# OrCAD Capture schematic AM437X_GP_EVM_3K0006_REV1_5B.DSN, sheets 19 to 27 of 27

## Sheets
19 Pg24: Keypad/LED's: size C
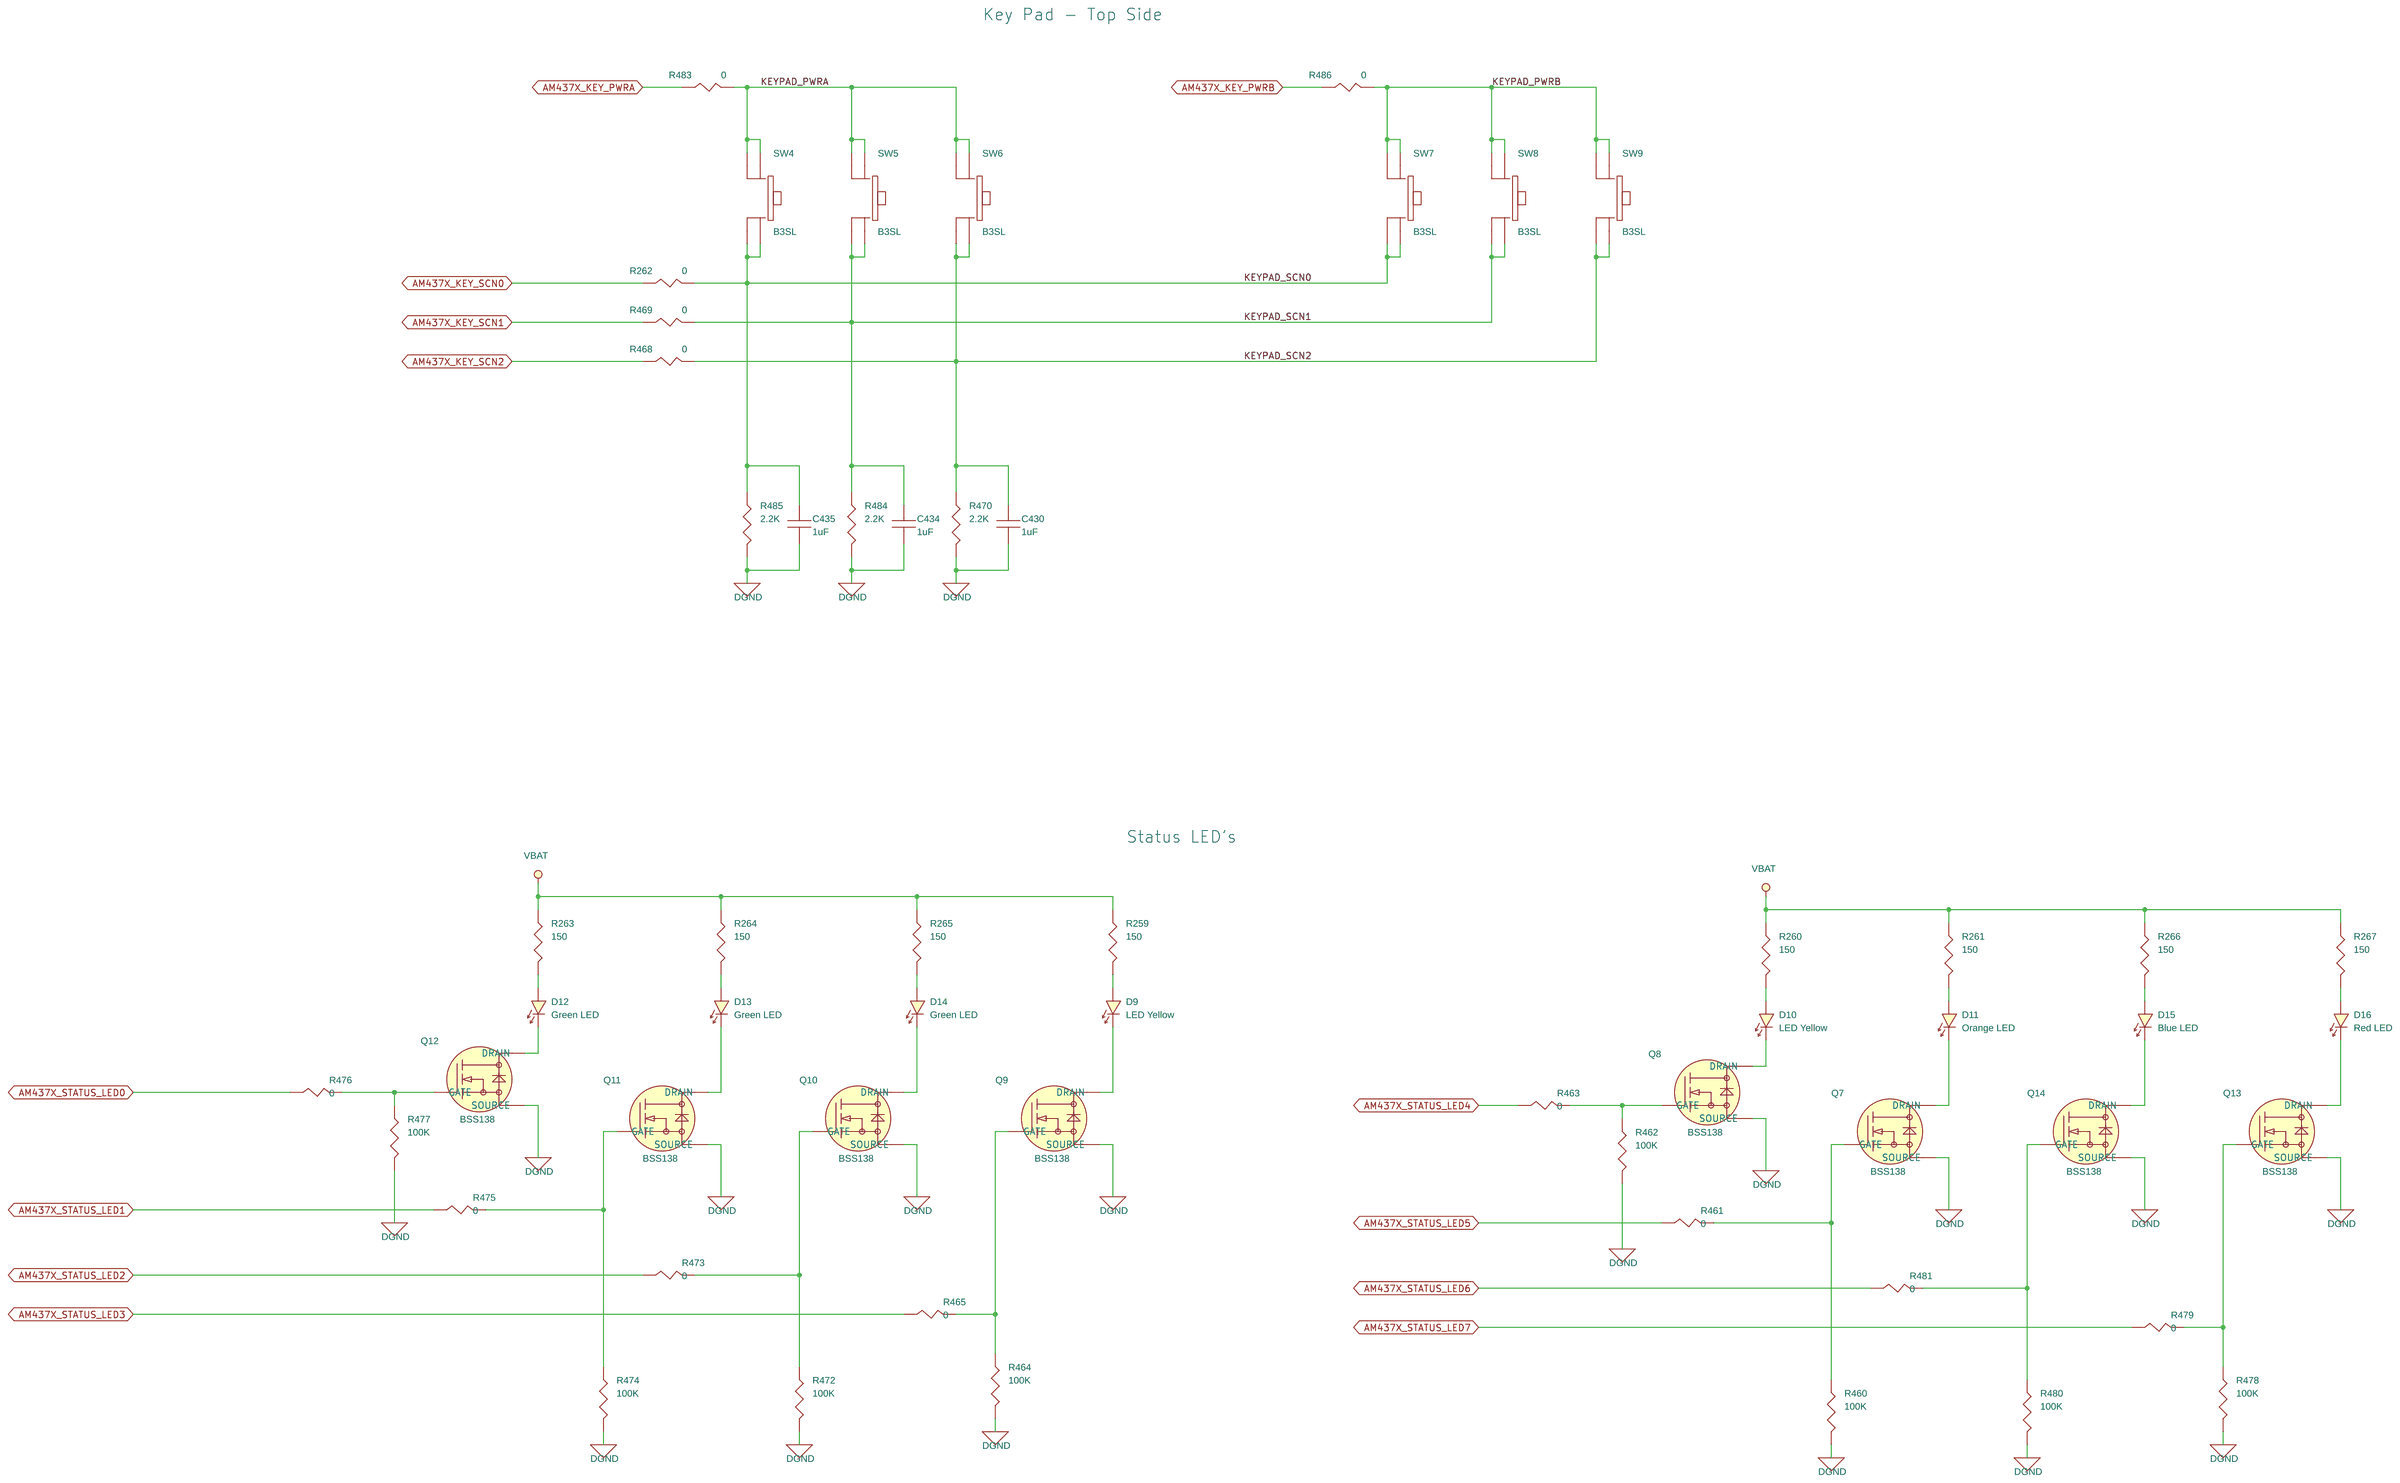
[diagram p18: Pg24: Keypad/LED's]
20 Pg27: Power Monitor: size C
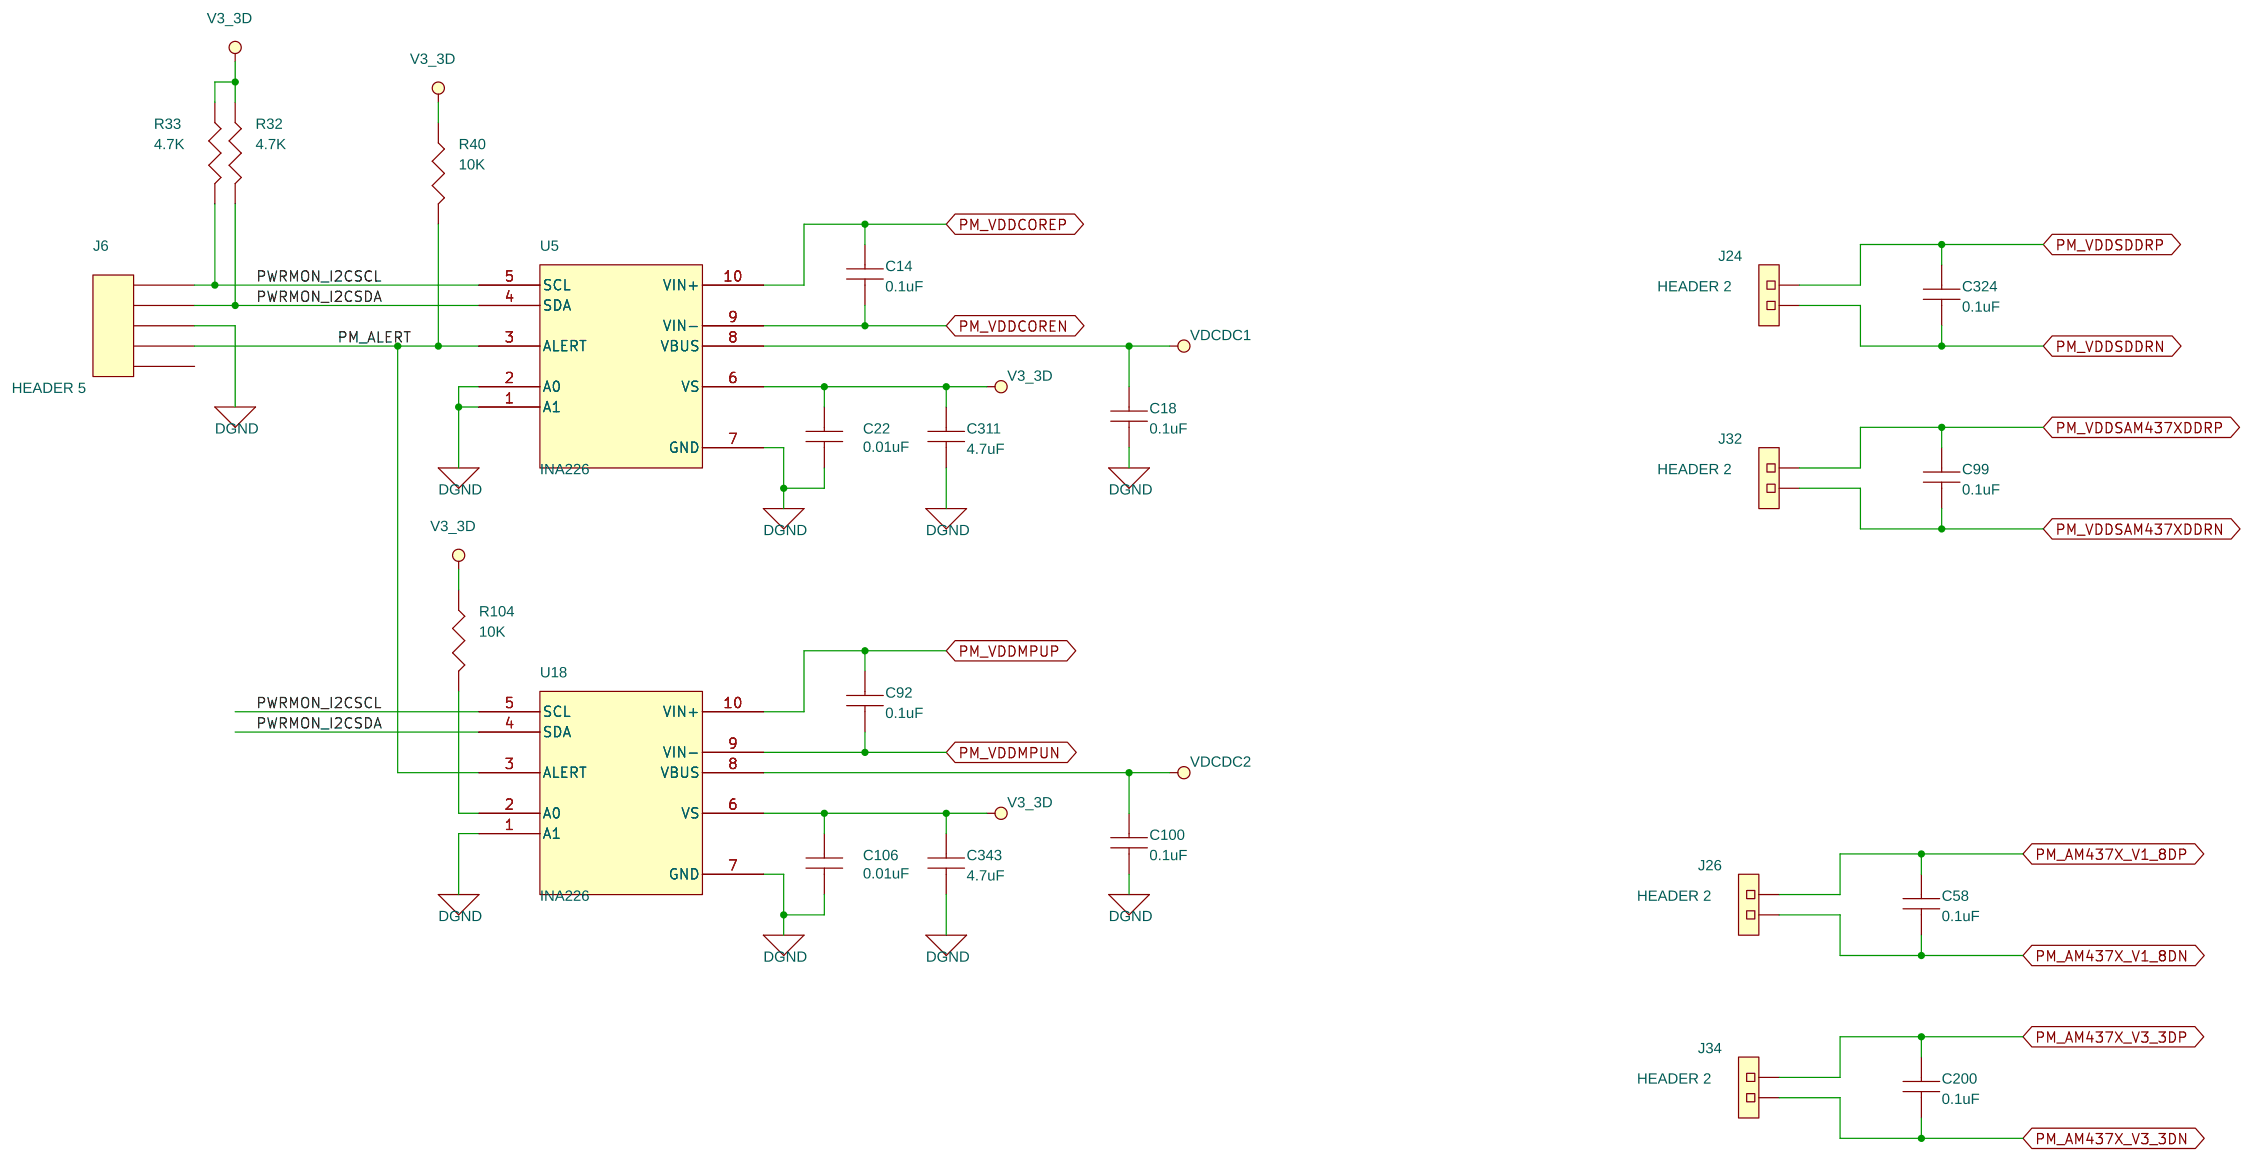
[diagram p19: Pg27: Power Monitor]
21 Pg23: Unused pins/GPIO: size C
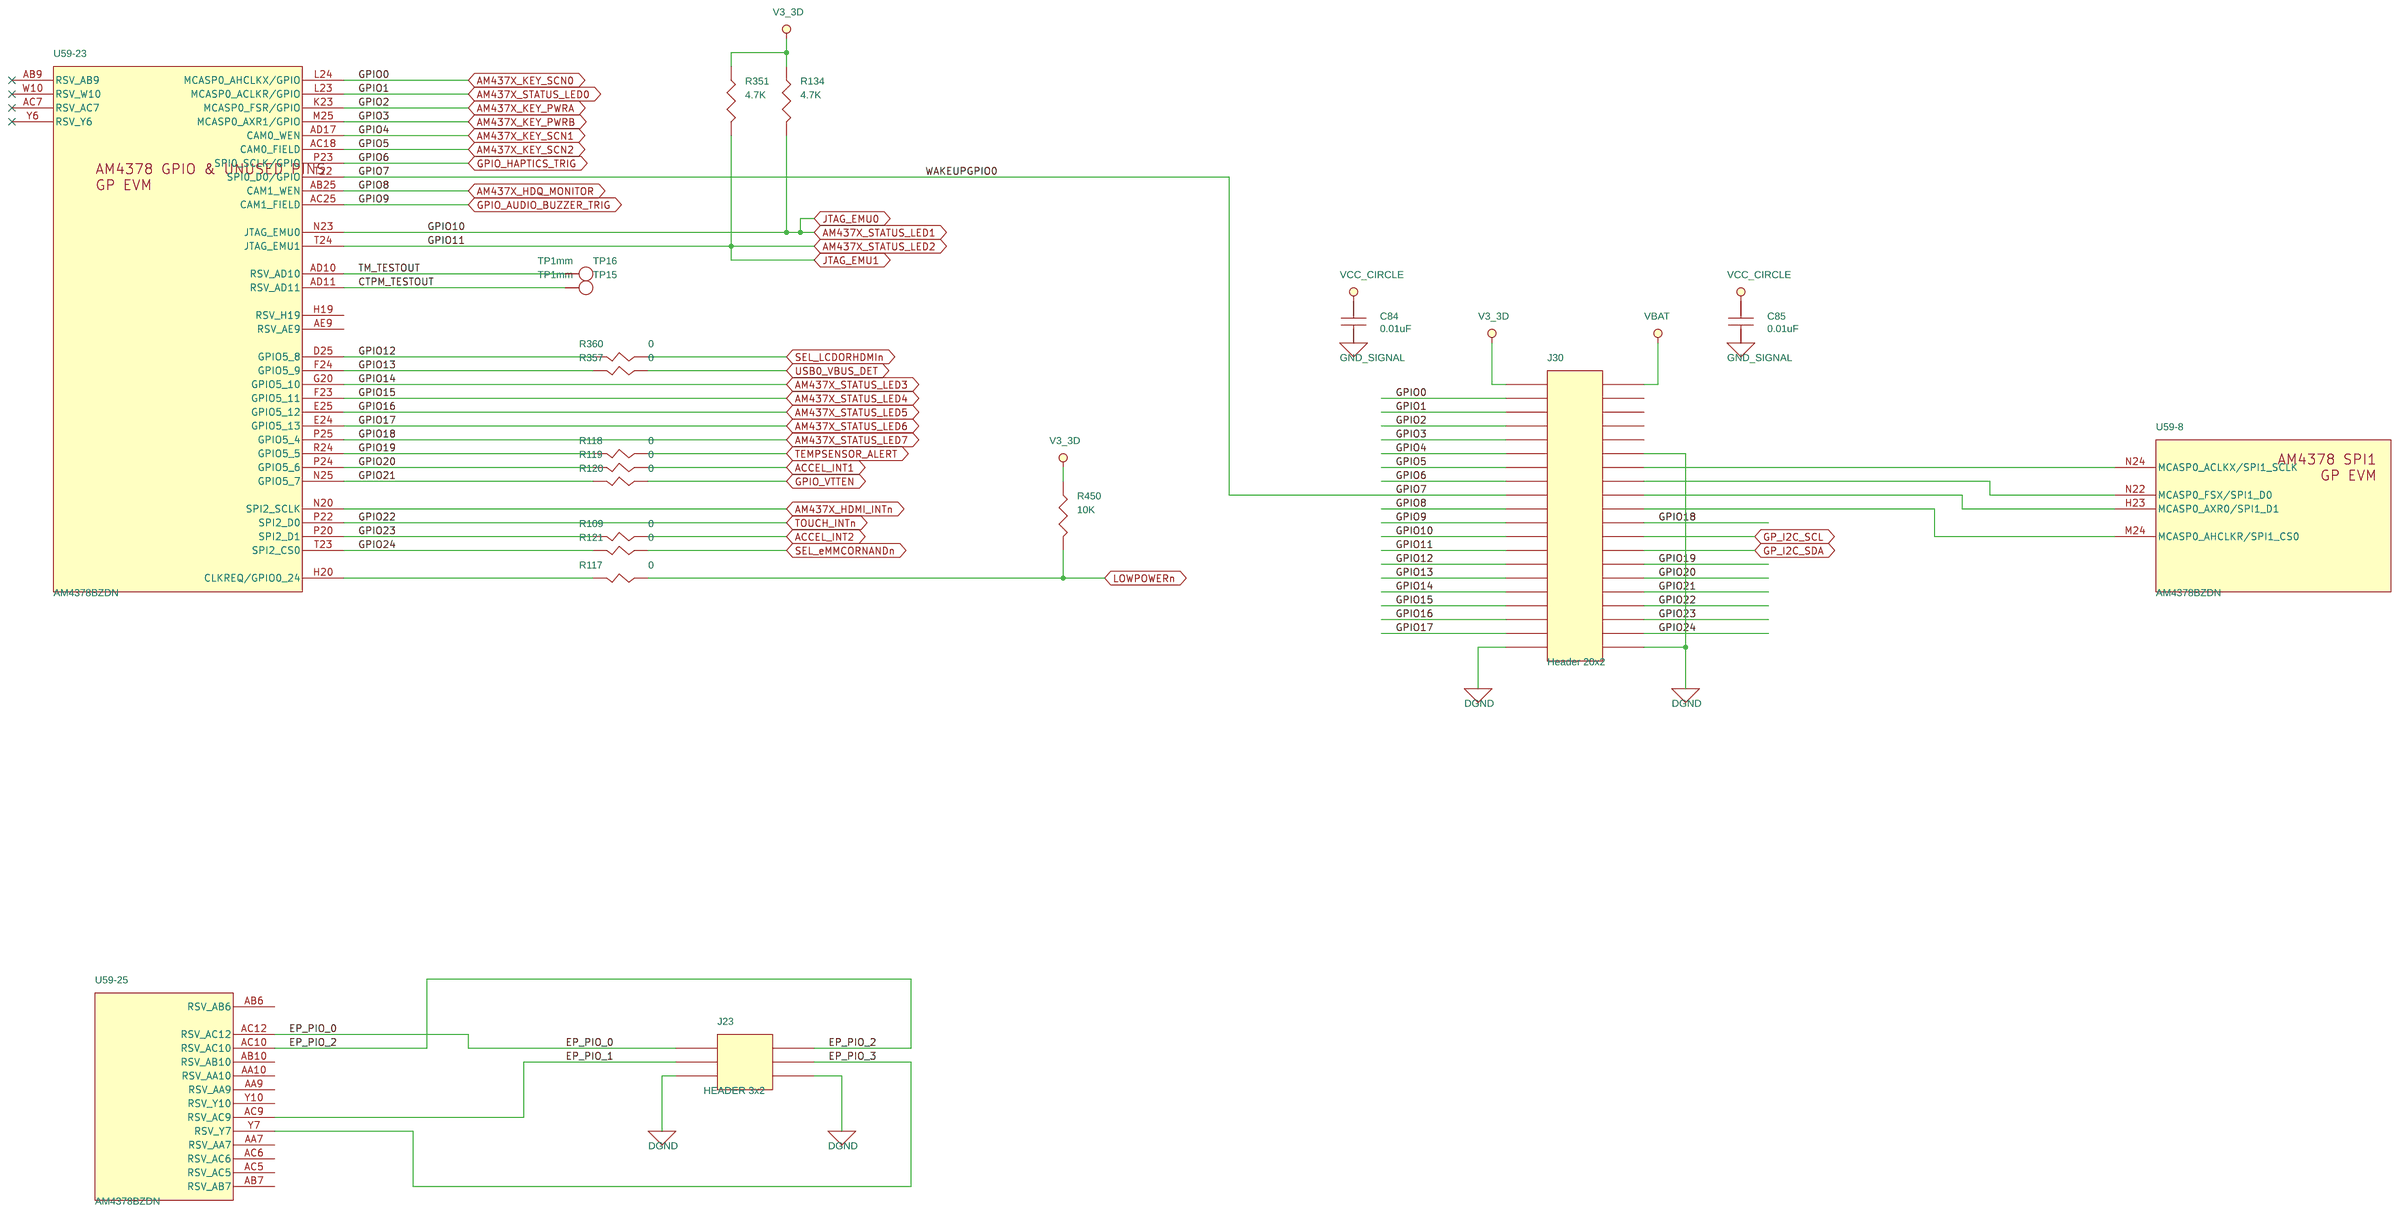
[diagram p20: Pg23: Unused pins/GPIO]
22 Pg08: SDMMC0 Interface: size C
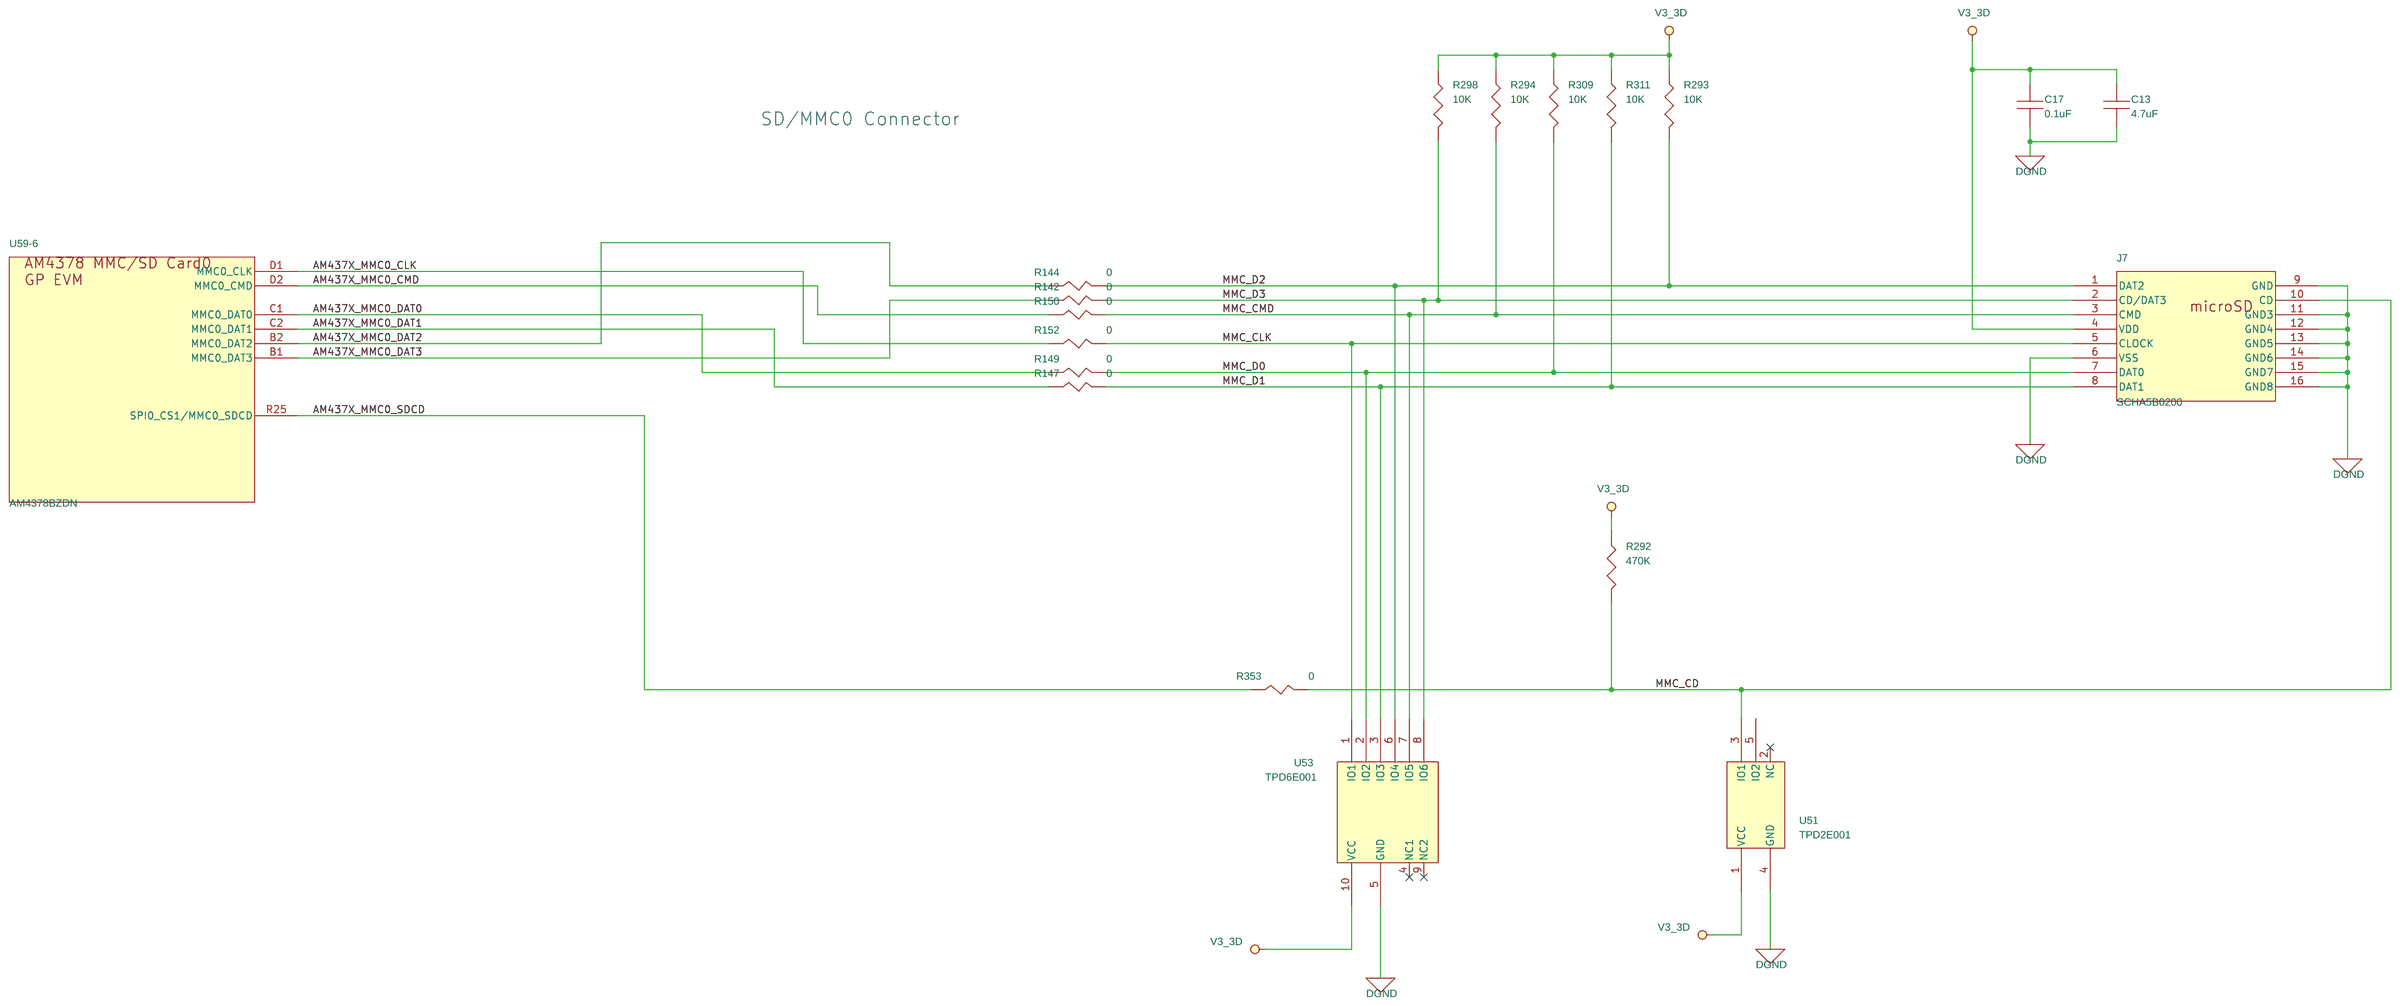
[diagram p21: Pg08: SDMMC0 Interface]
23 Pg04: Power Supply - PMIC: size C
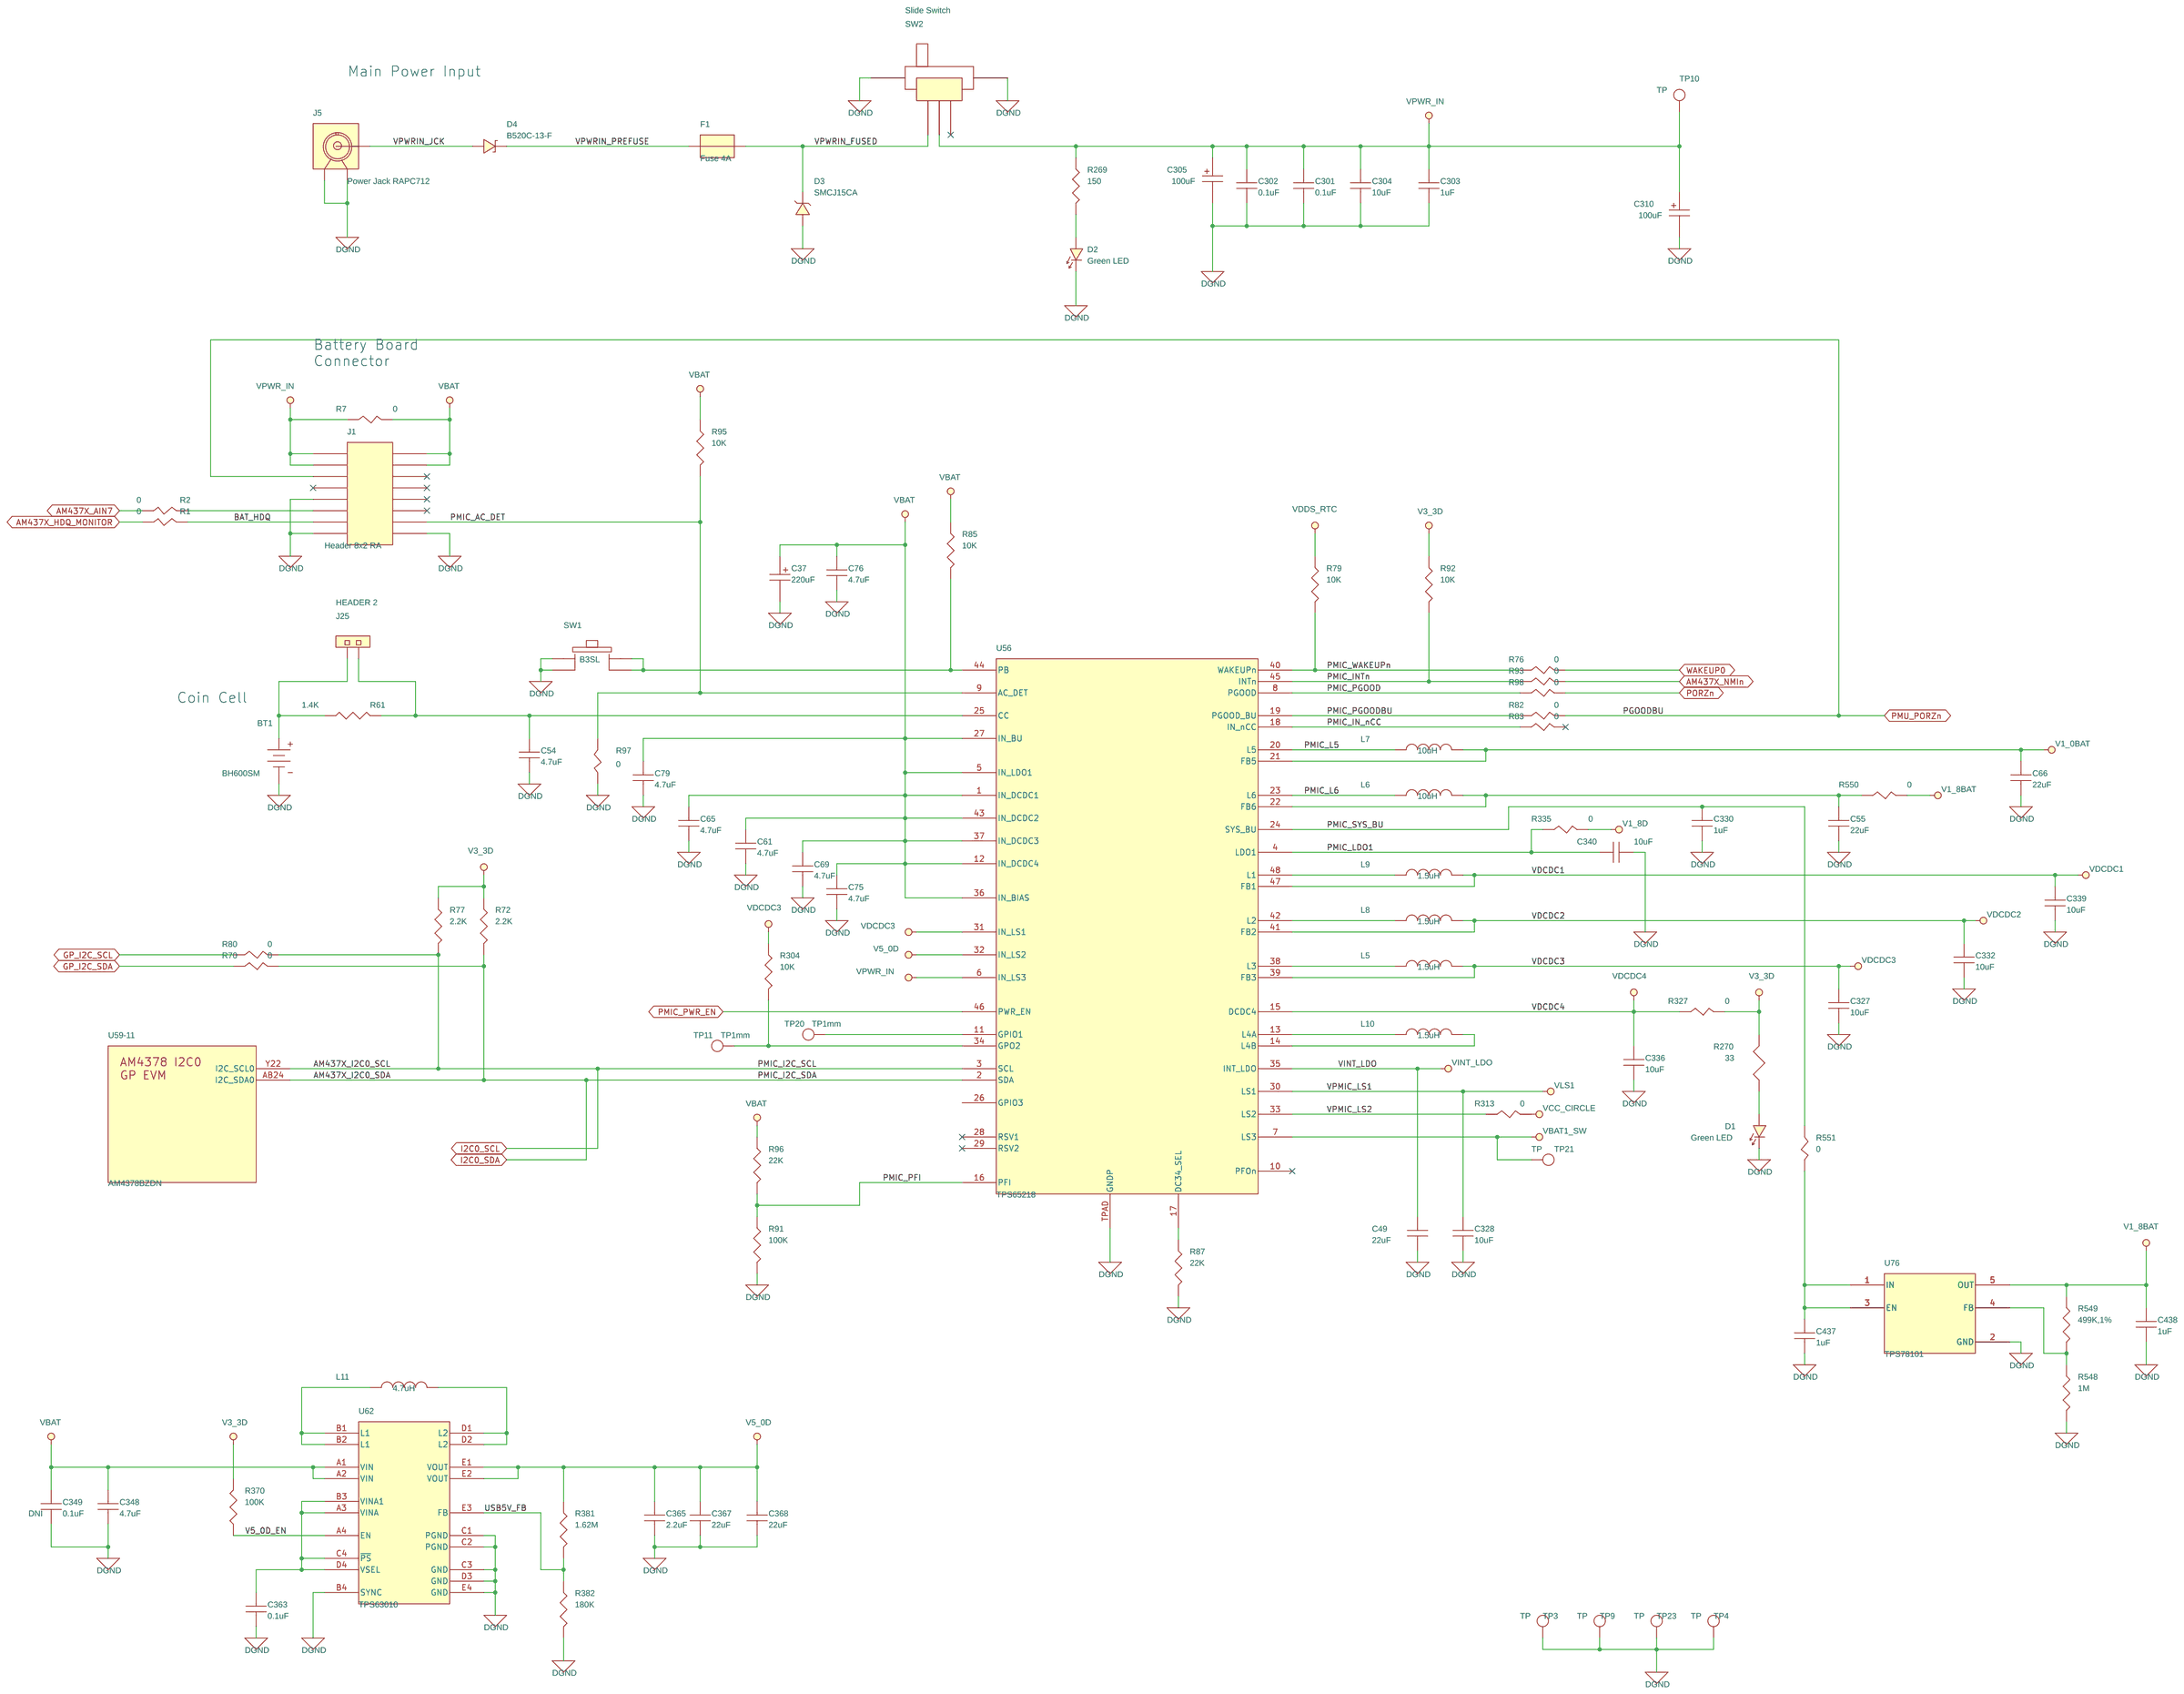
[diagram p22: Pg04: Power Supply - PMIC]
24 Pg02: Processor subsystem: size C
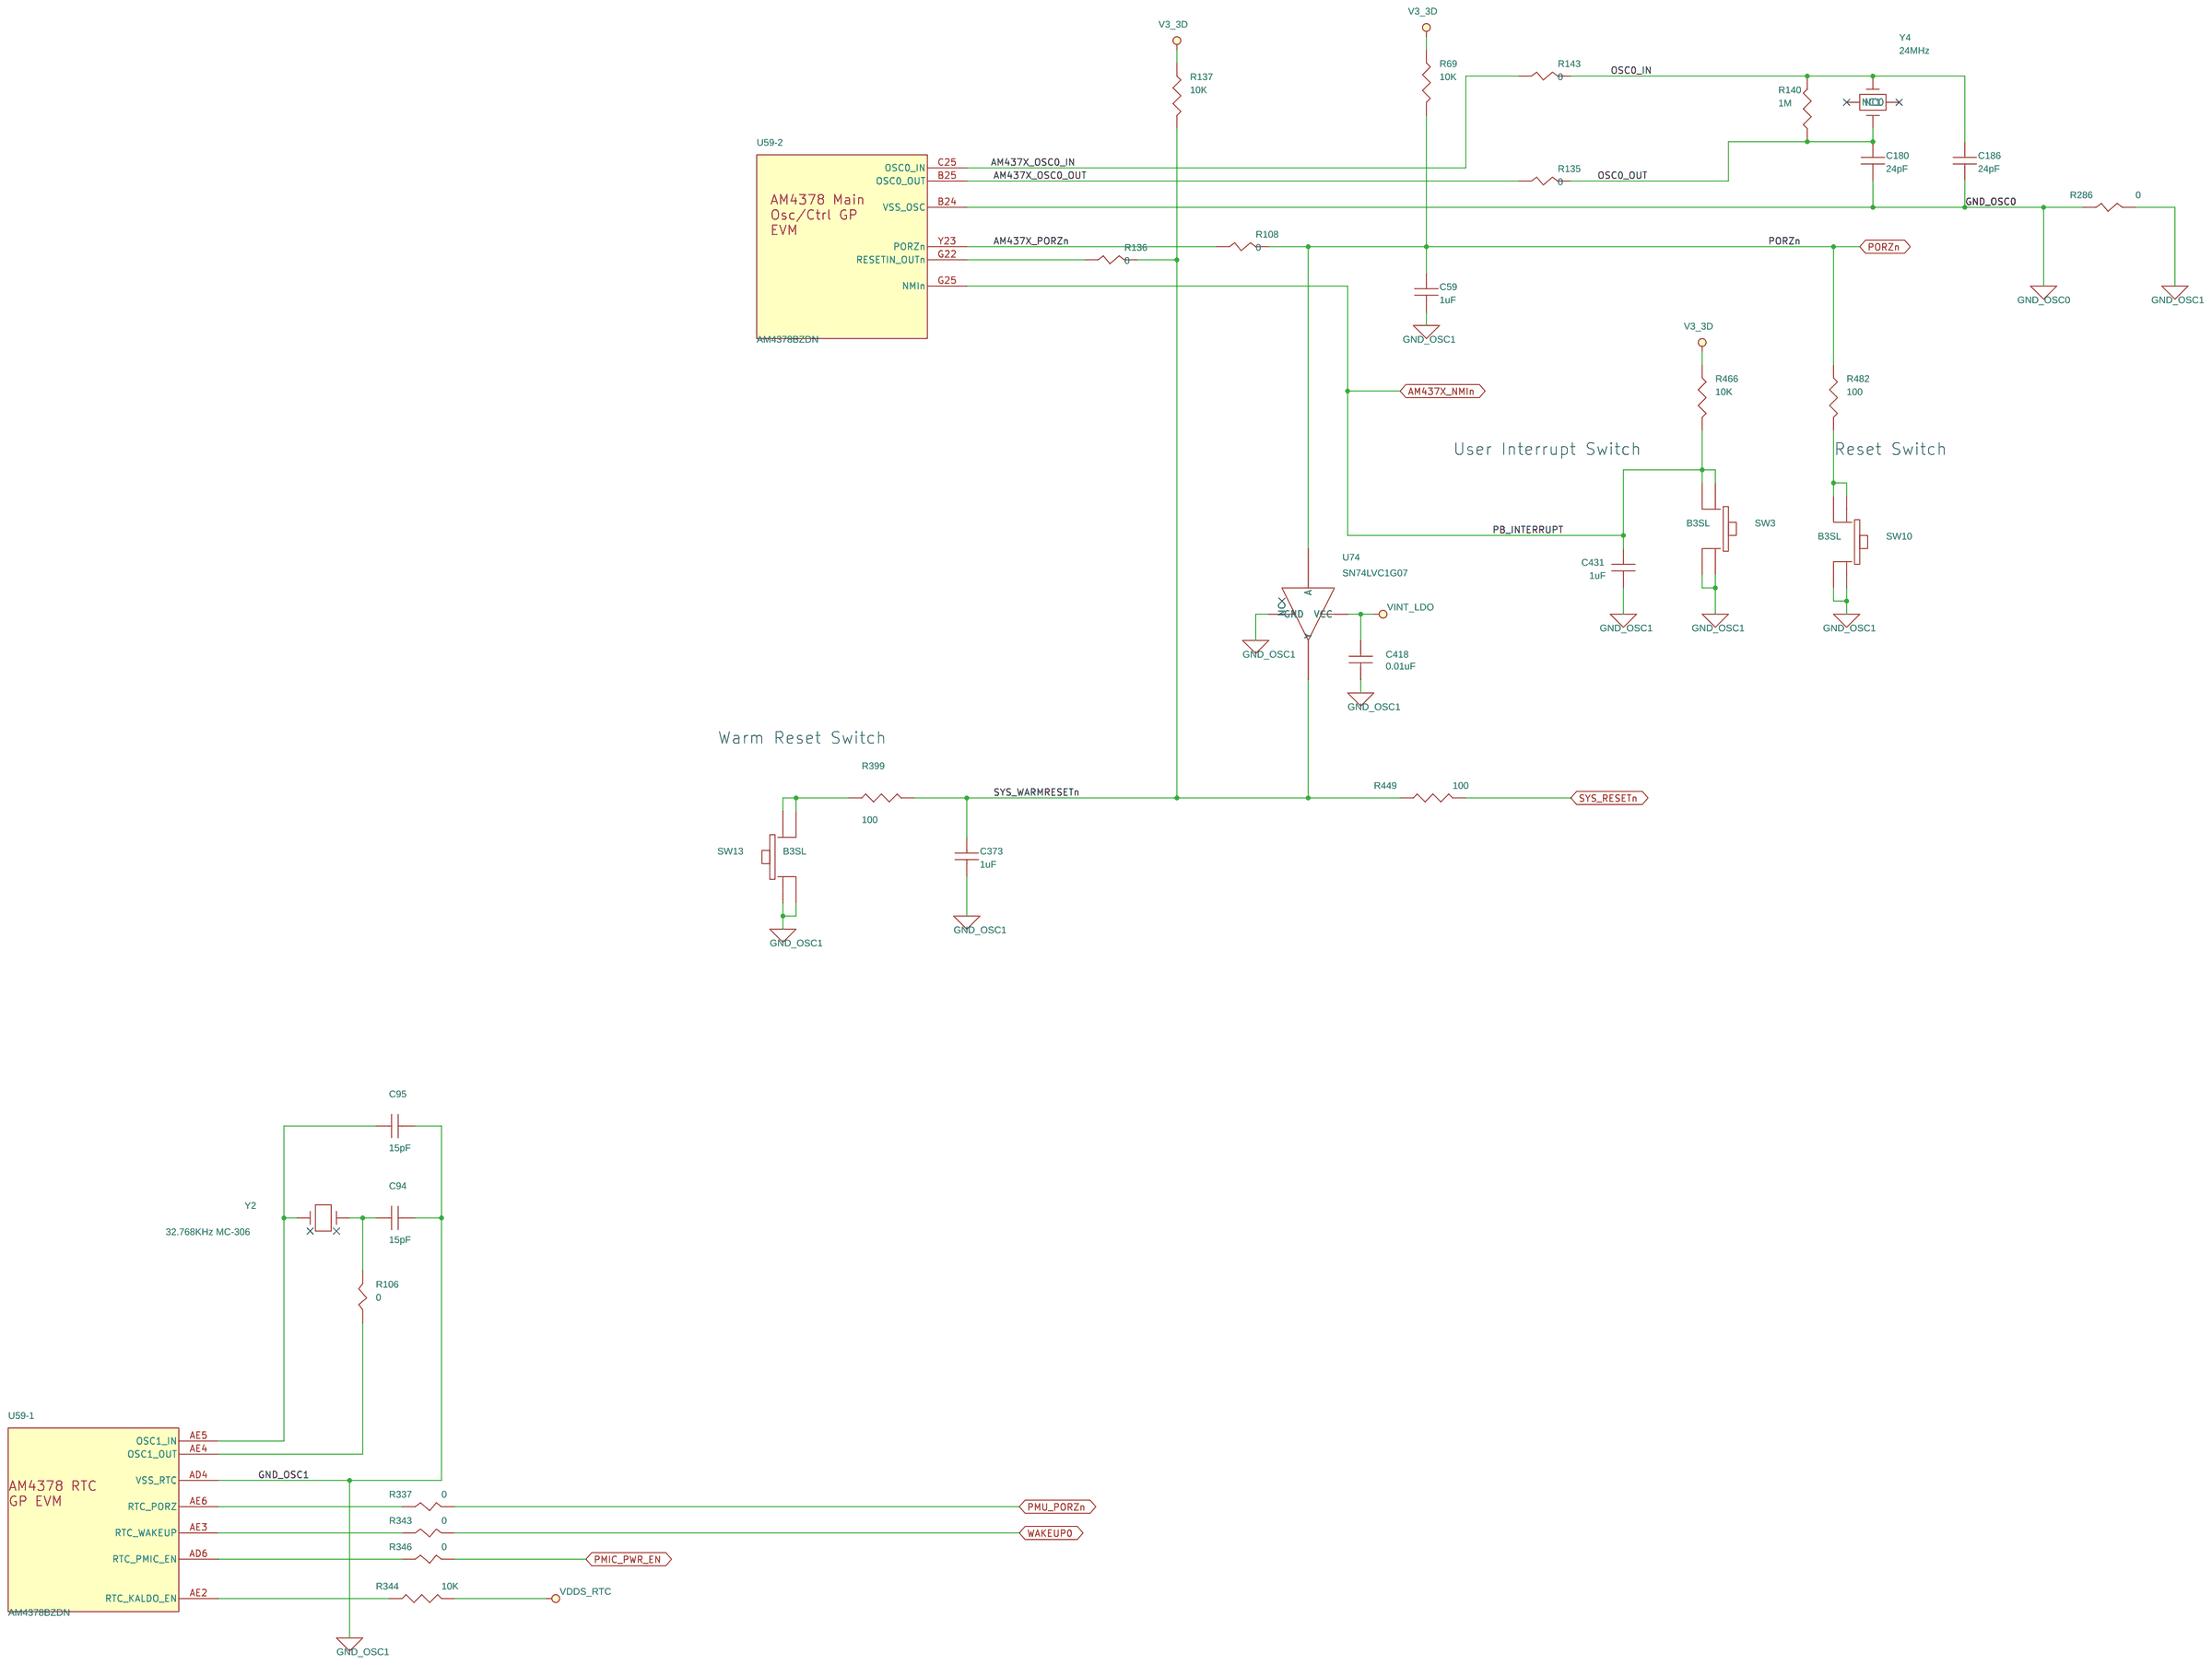
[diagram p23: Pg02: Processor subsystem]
25 Pg05: NAND Flash Memory & eMMC: size C
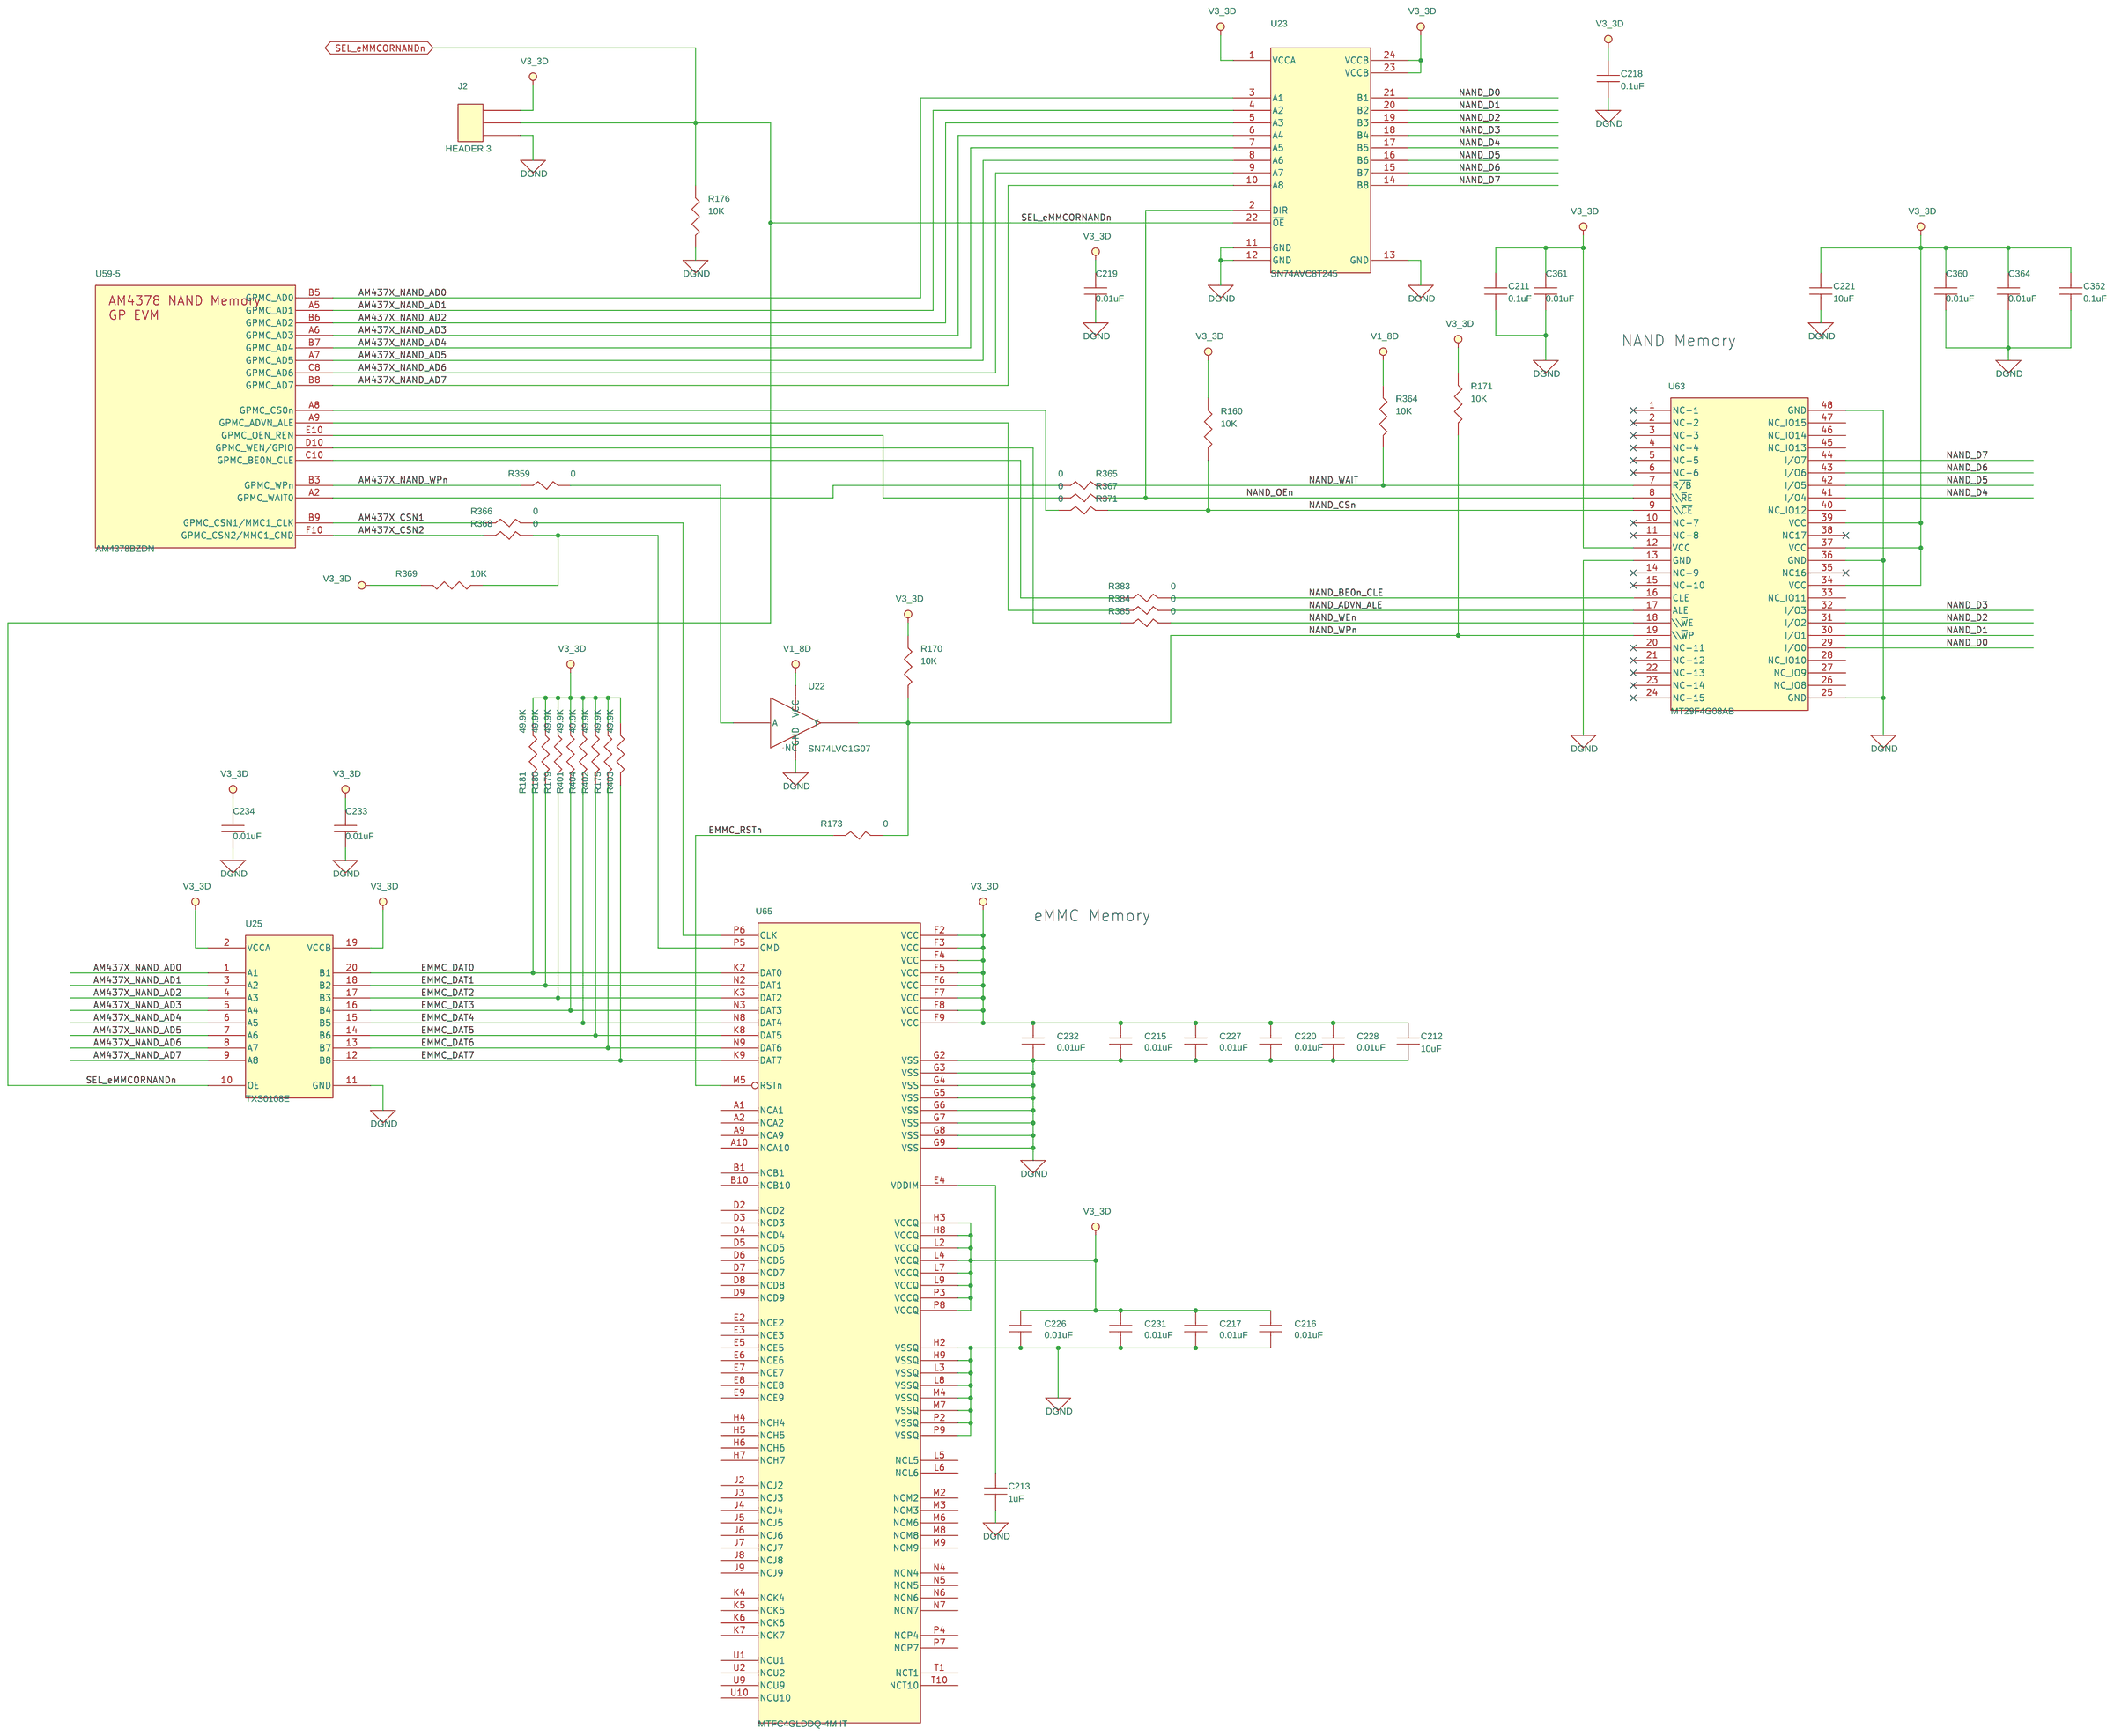
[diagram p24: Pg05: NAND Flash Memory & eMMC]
26 Pg20: Secondary RTC Osc/Ctrl: size C
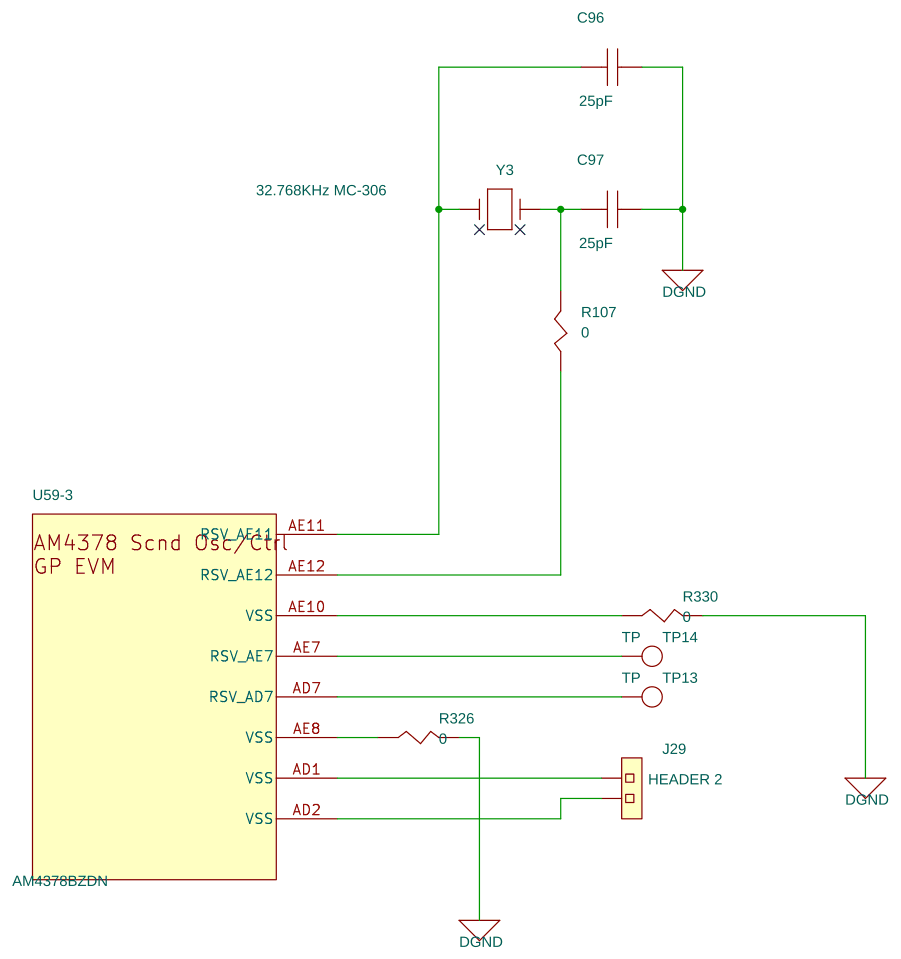
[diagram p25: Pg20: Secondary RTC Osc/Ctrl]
27 Pg10: Sensors, Buzzer, Haptics: size C
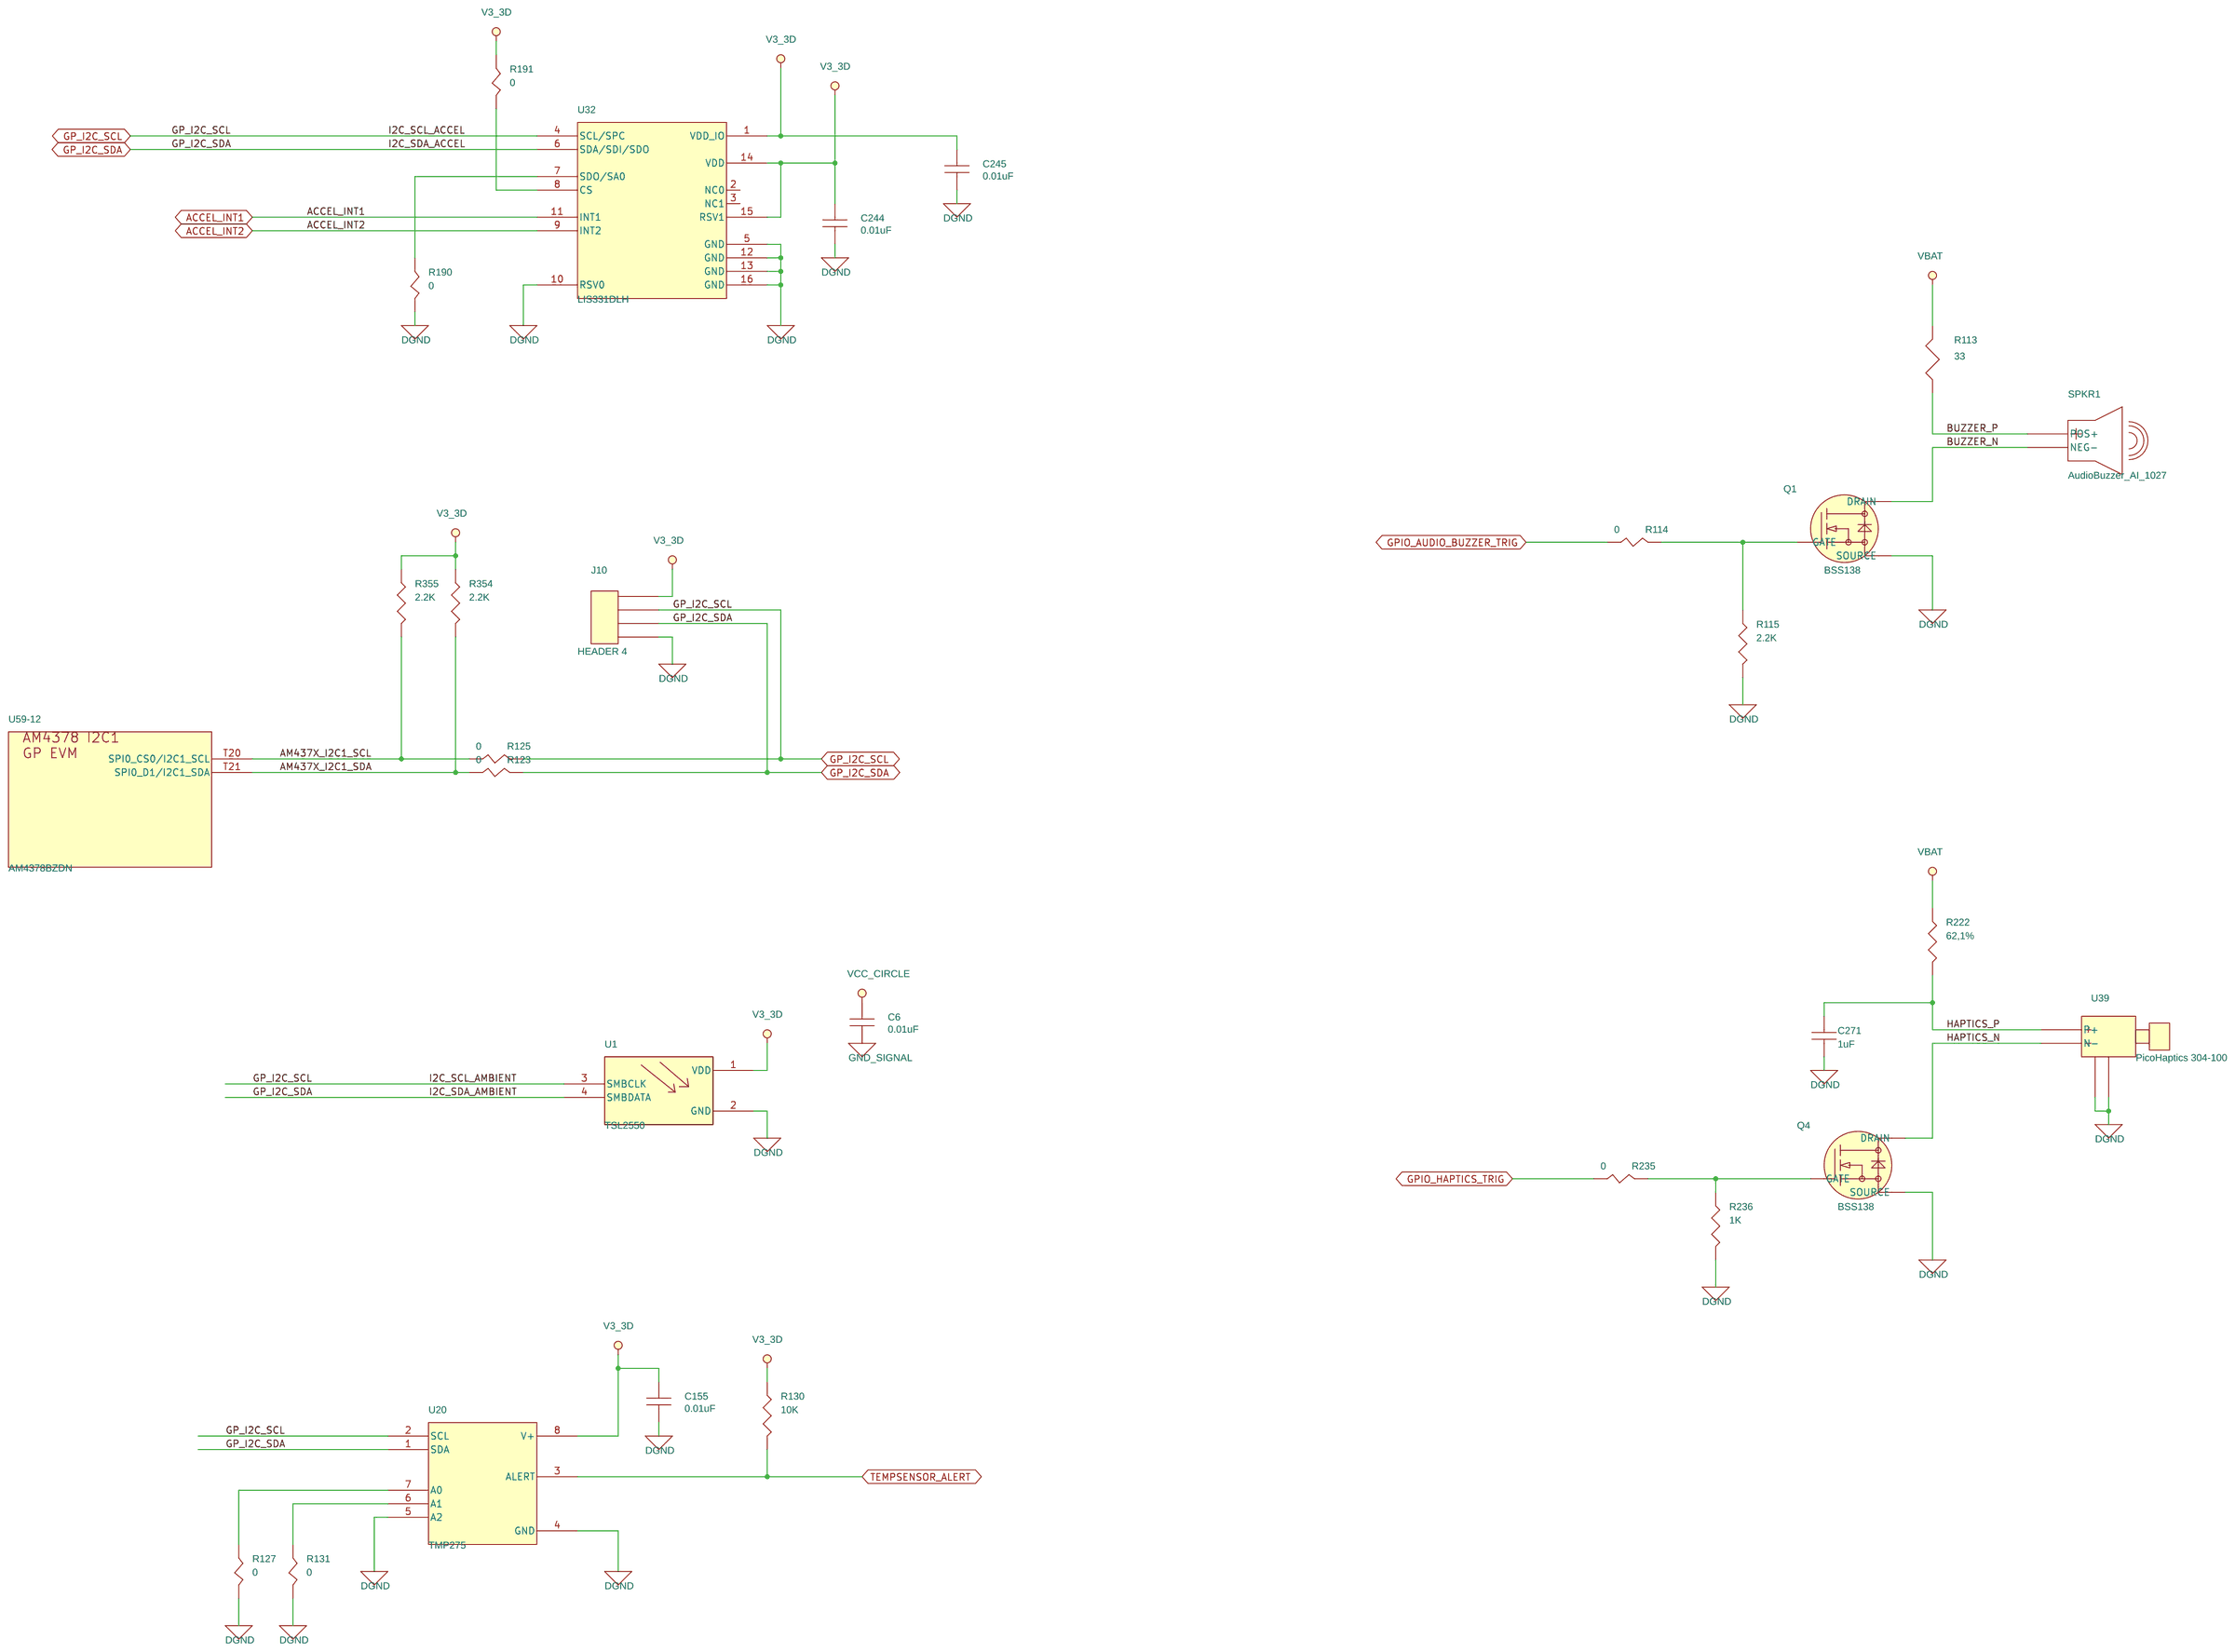
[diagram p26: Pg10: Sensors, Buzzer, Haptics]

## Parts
sheet Pg02: Processor subsystem
C59  1uF  [SM-7351-CAP-0402]
C94  15pF  [SM-7351-CAP-0402]
C95  15pF  [SM-7351-CAP-0402]
C180  24pF  [SM-7351-CAP-0402]
C186  24pF  [SM-7351-CAP-0402]
C373  1uF  [SM-7351-CAP-0402]
C418  0.01uF  [SM-7351-CAP-0402]
C431  1uF  [SM-7351-CAP-0402]
R69  10K  [SM-7351-RES-0402]
R106  0  [SM-7351-RES-0402]
R108  0  [SM-7351-RES-0402]
R135  0  [SM-7351-RES-0402]
R136  0  [SM-7351-RES-0402]
R137  10K  [SM-7351-RES-0402]
R140  1M  [SM-7351-RES-0402]
R143  0  [SM-7351-RES-0402]
R286  0  [SM-7351-RES-0402]
R337  0  [SM-7351-RES-0402]
R343  0  [SM-7351-RES-0402]
R344  10K  [SM-7351-RES-0402]
R346  0  [SM-7351-RES-0402]
R399  100  [SM-7351-RES-0402]
R449  100  [SM-7351-RES-0402]
R466  10K  [SM-7351-RES-0402]
R482  100  [SM-7351-RES-0402]
SW3  B3SL  [SW_B3SL-1022P]
SW10  B3SL  [SW_B3SL-1022P]
SW13  B3SL  [SW_B3SL-1022P]
U74  SN74LVC1G07  [SC70-5-43M]
Y2  32.768KHz MC-306  [MC-306]
Y4  24MHz  [XTAL2X3-30M]
sheet Pg04: Power Supply - PMIC
BT1  BH600SM  [bh600sm]
C37  220uF  [smd7343-122m]
C49  22uF  [SM-7351-CAP-0805]
C54  4.7uF  [SM-7351-CAP-0603]
C55  22uF  [SM-7351-CAP-0603]
C61  4.7uF  [SM-7351-CAP-0603]
C65  4.7uF  [SM-7351-CAP-0603]
C66  22uF  [SM-7351-CAP-0603]
C69  4.7uF  [SM-7351-CAP-0603]
C75  4.7uF  [SM-7351-CAP-0603]
C76  4.7uF  [SM-7351-CAP-0603]
C79  4.7uF  [SM-7351-CAP-0603]
C301  0.1uF  [SM-7351-CAP-0402]
C302  0.1uF  [SM-7351-CAP-0402]
C303  1uF  [SM-7351-CAP-0603]
C304  10uF  [SM-7351-CAP-0805]
C305  100uF  [SM-7351-CAP-smdcan]
C310  100uF  [SM-7351-CAP-smdcan]
C327  10uF  [SM-7351-CAP-0805]
C328  10uF  [SM-7351-CAP-0805]
C330  1uF  [SM-7351-CAP-0402]
C332  10uF  [SM-7351-CAP-0805]
C336  10uF  [SM-7351-CAP-0805]
C339  10uF  [SM-7351-CAP-0805]
C340  10uF  [SM-7351-CAP-0805]
C348  4.7uF  [SM-7351-CAP-0603]
C349  0.1uF  [SM-7351-CAP-0402]
C363  0.1uF  [SM-7351-CAP-0402]
C365  2.2uF  [SM-7351-CAP-0402]
C367  22uF  [SM-7351-CAP-0805]
C368  22uF  [SM-7351-CAP-0805]
C437  1uF  [SM-7351-CAP-0603]
C438  1uF  [SM-7351-CAP-0603]
D1  Green LED  [sm_led_0805]
D2  Green LED  [sm_led_0805]
D3  SMCJ15CA  [SMCJ15CA]
D4  B520C-13-F  [B520C-13-F]
F1  Fuse 4A  [smdfuseblk]
J1  Header 8x2 RA  [HDR2X8RA-201M]
J5  Power Jack RAPC712  [RAPC712]
J25  HEADER 2  [header_2x1]
L5  1.5uH  [IND_SPM3012T]
L6  10uH  [ind-mlz2012-57m]
L7  10uH  [ind-mlz2012-57m]
L8  1.5uH  [IND_SPM3012T]
L9  1.5uH  [IND_SPM3012T]
L10  1.5uH  [IND_SPM3012T]
L11  4.7uH  [smd_slf7055t]
R1  0  [SM-7351-RES-0402]
R2  0  [SM-7351-RES-0402]
R7  0  [SM-7351-RES-1210]
R61  1.4K  [SM-7351-RES-0402]
R70  0  [SM-7351-RES-0402]
R72  2.2K  [sm-7351-res-0402]
R76  0  [SM-7351-RES-0402]
R77  2.2K  [sm-7351-res-0402]
R79  10K  [SM-7351-RES-0402]
R80  0  [SM-7351-RES-0402]
R82  0  [SM-7351-RES-0402]
R83  0  [SM-7351-RES-0402]
R85  10K  [SM-7351-RES-0402]
R87  22K  [SM-7351-RES-0402]
R91  100K  [SM-7351-RES-0402]
R92  10K  [SM-7351-RES-0402]
R93  0  [SM-7351-RES-0402]
R95  10K  [SM-7351-RES-0402]
R96  22K  [SM-7351-RES-0402]
R97  0  [SM-7351-RES-0402]
R98  0  [SM-7351-RES-0402]
R269  150  [SM-7351-RES-0402]
R270  33  [SM-7351-RES-0402]
R304  10K  [SM-7351-RES-0402]
R313  0  [SM-7351-RES-0402]
R327  0  [SM-7351-RES-0603]
R335  0  [SM-7351-RES-0603]
R370  100K  [SM-7351-RES-0402]
R381  1.62M  [SM-7351-RES-0402]
R382  180K  [SM-7351-RES-0402]
R548  1M  [SM-7351-RES-0402]
R549  499K,1%  [SM-7351-RES-0402]
R550  0  [SM-7351-RES-0402]
R551  0  [SM-7351-RES-0402]
SW1  B3SL  [SW_B3SL-1022P]
SW2  Slide Switch  [TH_SW_T551101]
TP3  TP  [TH_TP_5002]
TP4  TP  [TH_TP_5002]
TP9  TP  [TH_TP_5002]
TP10  TP  [TH_TP_5002]
TP11  TP1mm  [tp_smd1mmcircle]
TP20  TP1mm  [tp_smd1mmcircle]
TP21  TP  [TH_TP_5002]
TP23  TP  [TH_TP_5002]
U56  TPS65218  [qfn6x6-48-39m]
U62  TPS63010  [u_20_dsbga]
U76  TPS78101  [sot23-5-43m]
sheet Pg05: NAND Flash Memory & eMMC
C211  0.1uF  [SM-7351-CAP-0402]
C212  10uF  [SM-7351-CAP-0805]
C213  1uF  [SM-7351-CAP-0402]
C215  0.01uF  [SM-7351-CAP-0402]
C216  0.01uF  [SM-7351-CAP-0402]
C217  0.01uF  [SM-7351-CAP-0402]
C218  0.1uF  [SM-7351-CAP-0402]
C219  0.01uF  [SM-7351-CAP-0402]
C220  0.01uF  [SM-7351-CAP-0402]
C221  10uF  [SM-7351-CAP-0805]
C226  0.01uF  [SM-7351-CAP-0402]
C227  0.01uF  [SM-7351-CAP-0402]
C228  0.01uF  [SM-7351-CAP-0402]
C231  0.01uF  [SM-7351-CAP-0402]
C232  0.01uF  [SM-7351-CAP-0402]
C233  0.01uF  [SM-7351-CAP-0402]
C234  0.01uF  [SM-7351-CAP-0402]
C360  0.01uF  [SM-7351-CAP-0402]
C361  0.01uF  [SM-7351-CAP-0402]
C362  0.1uF  [SM-7351-CAP-0402]
C364  0.01uF  [SM-7351-CAP-0402]
J2  HEADER 3  [header_3x1]
R160  10K  [SM-7351-RES-0402]
R170  10K  [SM-7351-RES-0402]
R171  10K  [SM-7351-RES-0402]
R173  0  [SM-7351-RES-0402]
R175  49.9K  [SM-7351-RES-0402]
R176  10K  [SM-7351-RES-0402]
R179  49.9K  [SM-7351-RES-0402]
R180  49.9K  [SM-7351-RES-0402]
R181  49.9K  [SM-7351-RES-0402]
R359  0  [SM-7351-RES-0402]
R364  10K  [SM-7351-RES-0402]
R365  0  [SM-7351-RES-0402]
R366  0  [SM-7351-RES-0402]
R367  0  [SM-7351-RES-0402]
R368  0  [SM-7351-RES-0402]
R369  10K  [SM-7351-RES-0402]
R371  0  [SM-7351-RES-0402]
R383  0  [SM-7351-RES-0402]
R384  0  [SM-7351-RES-0402]
R385  0  [SM-7351-RES-0402]
R401  49.9K  [SM-7351-RES-0402]
R402  49.9K  [SM-7351-RES-0402]
R403  49.9K  [SM-7351-RES-0402]
R404  49.9K  [SM-7351-RES-0402]
U22  SN74LVC1G07  [SC70-5-43M]
U23  SN74AVC8T245  [TSSOP8x4-24-47m]
U25  TXS0108E  [u_20_pw]
U63  MT29F4G08AB  [skt-tsop48sm]
U65  MTFC4GLDDQ-4M IT  [bga18x14-100-55m]
sheet Pg08: SDMMC0 Interface
C13  4.7uF  [SM-7351-CAP-0603]
C17  0.1uF  [SM-7351-CAP-0402]
J7  SCHA5B0200  [SD-MICRO-SCHA5B0300]
R142  0  [SM-7351-RES-0402]
R144  0  [SM-7351-RES-0402]
R147  0  [SM-7351-RES-0402]
R149  0  [SM-7351-RES-0402]
R150  0  [SM-7351-RES-0402]
R152  0  [SM-7351-RES-0402]
R292  470K  [SM-7351-RES-0402]
R293  10K  [SM-7351-RES-0402]
R294  10K  [SM-7351-RES-0402]
R298  10K  [SM-7351-RES-0402]
R309  10K  [SM-7351-RES-0402]
R311  10K  [SM-7351-RES-0402]
R353  0  [SM-7351-RES-0402]
U51  TPD2E001  [U_5_DRL]
U53  TPD6E001  [U_10_RSE]
U59  AM4378BZDN  [AM437X_ZDN]  (sections -1,-10,-11,-12,-13,-14,-15,-16,-17,-18,-19,-2,-20,-21,-22,-23,-24,-25,-3,-4,-5,-6,-7,-8,-9)
sheet Pg10: Sensors, Buzzer, Haptics
C6  0.01uF  [SM-7351-CAP-0402]
C155  0.01uF  [SM-7351-CAP-0402]
C244  0.01uF  [SM-7351-CAP-0402]
C245  0.01uF  [SM-7351-CAP-0402]
C271  1uF  [SM-7351-CAP-0603]
J10  HEADER 4  [HDR1x4-330M]
Q1  BSS138  [SOT23-3]
Q4  BSS138  [SOT23-3]
R113  33  [SM-7351-RES-0402]
R114  0  [SM-7351-RES-0402]
R115  2.2K  [sm-7351-res-0402]
R123  0  [SM-7351-RES-0402]
R125  0  [SM-7351-RES-0402]
R127  0  [SM-7351-RES-0402]
R130  10K  [SM-7351-RES-0402]
R131  0  [SM-7351-RES-0402]
R190  0  [SM-7351-RES-0402]
R191  0  [SM-7351-RES-0402]
R222  62,1%  [sm-7351-res-0402]
R235  0  [SM-7351-RES-0402]
R236  1K  [SM-7351-RES-0402]
R354  2.2K  [sm-7351-res-0402]
R355  2.2K  [sm-7351-res-0402]
SPKR1  AudioBuzzer_AI_1027  [spkr_ai_1027]
U1  TSL2550  [smd4x3-4-59m]
U20  TMP275  [MSOP_dgk]
U32  LIS331DLH  [LGA16pin_3x3]
U39  PicoHaptics 304-100  [pico_304-100]
sheet Pg20: Secondary RTC Osc/Ctrl
C96  25pF  [SM-7351-CAP-0603]
C97  25pF  [SM-7351-CAP-0603]
J29  HEADER 2  [header_2x1]
R107  0  [SM-7351-RES-0402]
R326  0  [SM-7351-RES-0402]
R330  0  [SM-7351-RES-0402]
TP13  TP  [TH_TP_5002]
TP14  TP  [TH_TP_5002]
Y3  32.768KHz MC-306  [MC-306]
sheet Pg23: Unused pins/GPIO
C84  0.01uF  [SM-7351-CAP-0402]
C85  0.01uF  [SM-7351-CAP-0402]
J23  HEADER 3x2  [hdr2x3-330m]
J30  Header 20x2  [HDR2X20-330M]
R109  0  [SM-7351-RES-0402]
R117  0  [SM-7351-RES-0402]
R118  0  [SM-7351-RES-0402]
R119  0  [SM-7351-RES-0402]
R120  0  [SM-7351-RES-0402]
R121  0  [SM-7351-RES-0402]
R134  4.7K  [SM-7351-RES-0402]
R351  4.7K  [SM-7351-RES-0402]
R357  0  [SM-7351-RES-0402]
R360  0  [SM-7351-RES-0402]
R450  10K  [SM-7351-RES-0402]
TP15  TP1mm  [tp_smd1mmcircle]
TP16  TP1mm  [tp_smd1mmcircle]
sheet Pg24: Keypad/LED's
C430  1uF  [SM-7351-CAP-0402]
C434  1uF  [SM-7351-CAP-0402]
C435  1uF  [SM-7351-CAP-0402]
D9  LED Yellow  [sm_led_0805]
D10  LED Yellow  [sm_led_0805]
D11  Orange LED  [sm_led_0805]
D12  Green LED  [sm_led_0805]
D13  Green LED  [sm_led_0805]
D14  Green LED  [sm_led_0805]
D15  Blue LED  [sm_led_0805]
D16  Red LED  [sm_led_0805]
Q7  BSS138  [SOT23-3]
Q8  BSS138  [SOT23-3]
Q9  BSS138  [SOT23-3]
Q10  BSS138  [SOT23-3]
Q11  BSS138  [SOT23-3]
Q12  BSS138  [SOT23-3]
Q13  BSS138  [SOT23-3]
Q14  BSS138  [SOT23-3]
R259  150  [SM-7351-RES-0402]
R260  150  [SM-7351-RES-0402]
R261  150  [SM-7351-RES-0402]
R262  0  [SM-7351-RES-0402]
R263  150  [SM-7351-RES-0402]
R264  150  [SM-7351-RES-0402]
R265  150  [SM-7351-RES-0402]
R266  150  [SM-7351-RES-0402]
R267  150  [SM-7351-RES-0402]
R460  100K  [SM-7351-RES-0402]
R461  0  [SM-7351-RES-0402]
R462  100K  [SM-7351-RES-0402]
R463  0  [SM-7351-RES-0402]
R464  100K  [SM-7351-RES-0402]
R465  0  [SM-7351-RES-0402]
R468  0  [SM-7351-RES-0402]
R469  0  [SM-7351-RES-0402]
R470  2.2K  [sm-7351-res-0402]
R472  100K  [SM-7351-RES-0402]
R473  0  [SM-7351-RES-0402]
R474  100K  [SM-7351-RES-0402]
R475  0  [SM-7351-RES-0402]
R476  0  [SM-7351-RES-0402]
R477  100K  [SM-7351-RES-0402]
R478  100K  [SM-7351-RES-0402]
R479  0  [SM-7351-RES-0402]
R480  100K  [SM-7351-RES-0402]
R481  0  [SM-7351-RES-0402]
R483  0  [SM-7351-RES-0402]
R484  2.2K  [sm-7351-res-0402]
R485  2.2K  [sm-7351-res-0402]
R486  0  [SM-7351-RES-0402]
SW4  B3SL  [SW_B3SL-1022P]
SW5  B3SL  [SW_B3SL-1022P]
SW6  B3SL  [SW_B3SL-1022P]
SW7  B3SL  [SW_B3SL-1022P]
SW8  B3SL  [SW_B3SL-1022P]
SW9  B3SL  [SW_B3SL-1022P]
sheet Pg27: Power Monitor
C14  0.1uF  [SM-7351-CAP-0402]
C18  0.1uF  [SM-7351-CAP-0402]
C22  0.01uF  [SM-7351-CAP-0402]
C58  0.1uF  [SM-7351-CAP-0402]
C92  0.1uF  [SM-7351-CAP-0402]
C99  0.1uF  [SM-7351-CAP-0402]
C100  0.1uF  [SM-7351-CAP-0402]
C106  0.01uF  [SM-7351-CAP-0402]
C200  0.1uF  [SM-7351-CAP-0402]
C311  4.7uF  [SM-7351-CAP-0603]
C324  0.1uF  [SM-7351-CAP-0402]
C343  4.7uF  [SM-7351-CAP-0603]
J6  HEADER 5  [HEADER_5X1]
J24  HEADER 2  [header_2x1]
J26  HEADER 2  [header_2x1]
J32  HEADER 2  [header_2x1]
J34  HEADER 2  [header_2x1]
R32  4.7K  [SM-7351-RES-0402]
R33  4.7K  [SM-7351-RES-0402]
R40  10K  [SM-7351-RES-0402]
R104  10K  [SM-7351-RES-0402]
U5  INA226  [MSOP3X3-10-43M]
U18  INA226  [MSOP3X3-10-43M]

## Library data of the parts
C59 C213 C330 C373 C430 C431 C434 C435 = 1C_1uFCapacitor10V10%0402
C94 C95 = 1C_15pFCapacitor50V10%smd0402
C180 C186 = 1C_24pFCapacitor50V5%SMD0402
C6 C22 C84 C85 C106 C155 C215-C217 C219 C220 C226-C228 C231-C234 C244 C245 C360 C361 C364 C418 = 1C_0.01uFCapacitor16V10%0402
R40 R69 R79 R85 R92 R95 R104 R130 R137 R160 R170 R171 R176 R293 R294 R298 R304 R309 R311 R344 R364 R369 R450 R466 = 1R_10KOhmResistor1_16W0402
R1 R2 R70 R76 R80 R82 R83 R93 R97 R98 R106-R109 R114 R117-R121 R123 R125 R127 R131 R135 R136 R142-R144 R147 R149 R150 R152 R173 R190 R191 R235 R262 R286 R313 R326 R330 R337 R343 R346 R353 R357 R359 R360 R365-R368 R371 R383-R385 R461 R463 R465 R468 R469 R473 R475 R476 R479 R481 R483 R486 R550 R551 = 1R_ZeroOhmResistor1_16W0402
R140 = 1MOhmResistor1_16W0402
R399 R449 R482 = 1R_100ohm1_16W1%SMD0402
SW1 SW3-SW10 SW13 = 2W_Switch_Pushbuttonsmd
U22 U74 = 1A_SN74LVC1G07
Y2 Y3 = 1Y_Crystal_SMD32_768kHz
Y4 = 1Y_Crystal24MHzSCM
BT1 = 1P_BatteryCR1632Holder
C37 = 1C_220uFCapacitor16V10%Tantalum
C49 C367 C368 = 1C_22uFCapacitor16V10%0805
C13 C54 C61 C65 C69 C75 C76 C79 C311 C343 C348 = 1C_4.7uFCapacitor16V10%0603
C55 C66 = 1C_22uFCapacitor6.3V20%0603
C14 C17 C18 C58 C92 C99 C100 C200 C211 C218 C301 C302 C324 C362 C363 = 1C_0.1uFCapacitor16V10%0402
C271 C303 C437 C438 = 1C_1uFCapacitor50V10%0603
C212 C221 C304 C327 C328 C332 C336 C339 C340 = 1C_10uFCapacitor16V10%0805
C305 C310 = 1C_100uFCapacitor16V20%ElecPoly
C349 = 1C_0.1uFCapacitor16V10%0402: Installed: DNI
C365 = 1C_2.2uFCapacitor6.3V20%X5R0402
D1 D2 D12-D14 = 1F_LED_Green
D3 = 1E_Diode_SMCJ15CA
D4 = 1E_Diode_5ARect
F1 = 1P_Fuse_4A
J1 = 2H_Header8x2pin_RA
J5 = 2J_Conn_PwrJack_RAPC712
J24-J26 J29 J32 J34 = 2H_Header_2x1
L5 L8-L10 = 1L_1.5uHInductor20%2.8Asmd
L6 L7 = 1L_10uHInductor20%110mAsmd
L11 = 1L_4.7uHInductor30%3.1Asmd
R7 = 1R_ZeroOhmResistor1_2W1210
R61 = 1R_1.4KOhmResistor1_16W1%0402
R72 R77 R115 R354 R355 R470 R484 R485 = 1R_2.2KOhmResistor1_16W0402
R87 R96 = 1R_22Kohm1_16W1%SMD0402
R91 R370 R460 R462 R464 R472 R474 R477 R478 R480 = 1R_100KOhmResistor1_16W0402
R259-R261 R263-R267 R269 = 1R_150ohm1_16W1%SMD0402
R113 R270 = 1R_33ohmResistor1_16W5%0402
R327 R335 = 1R_ZeroOhmResistor1_16W0603
R381 = 1R_1.62MOhmResistor1_16W0402
R382 = 1R_180KOhmResistor1_16W0402
R548 = 1R_1MOhmResistor1_16W0402
R549 = 1R_499Kohm1_16W1%smd0402
SW2 = 2W_Switch_SlideRA_SPDT
TP3 TP4 TP9 TP10 TP13 TP14 TP21 TP23 = 2H_TestPointThroughHole
TP11 TP15 TP16 TP20 = 2H_Testpoint_SMD1mmCircle
U56 = 1A_TPS65218
U62 = 1A_TPS63010YFF
U76 = 1A_TPS78101
J2 = 2H_Header_3x1
R175 R179-R181 R401-R404 = 1R_49.9KOhmResistor1_16W0402
U23 = 1A_SN74AVC8T245
U25 = 1A_TXS0108
U63 = 1A_MT29F4G08ABAE
U65 = 1A_MTFC4GLDDQ-4M
J7 = 2C_Conn_microSD_8
R292 = 470Kohm1_16W1%SMD0402
U51 = 1A_TPD2E001DRL
U53 = 1A_TPD6E001RSE
U59 = AM4378_ZDN_GPEVM
J10 = 2H_Header_4x1
Q1 Q4 Q7-Q14 = 1Q_MOSFET_NChan_BSS138
R222 = 1R_62OhmResistor1_16W0402
R236 = 1R_1KOhmResistor1_16W0402
SPKR1 = 1G_AudioBuzzer_AI_1027
U1 = 1A_TSL2550
U20 = 1A_TMP275
U32 = 1A_LIS331DLH
U39 = 1G_Haptics_Pico_304-100
C96 C97 = 1C_25pFCapacitor100V5%0603
J23 = 2H_Header3x2
J30 = 2H_Header20x2
R32 R33 R134 R351 = 1R_4.7KOhmResistor1_16W0402
D9 D10 = 1F_LED_Yellow
D11 = 1F_LED_Orange
D15 = 1F_LED_Blue
D16 = 1F_LED_Red
J6 = 2H_Header_5x1
U5 U18 = 1A_INA226

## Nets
DGND: BT1.2(Neg) C6.2 C13.2 C17.2 C18.2 C22.2 C37.2(NEG) C49.2 C54.2 C55.2 C59.2 C61.2 C65.2 C66.2 C69.2 C75.2 C76.2 C79.2 C84.2 C85.2 C94.2 C95.2 C96.1 C97.1 C100.2 C106.2 C155.2 C211.2 C212.2 C213.2 C215.2 C216.2 C217.2 C218.2 C219.2 C220.2 C221.2 C226.2 C227.2 C228.2 C231.2 C232.2 C233.2 C234.2 C244.2 C245.2 C271.2 C301.2 C302.2 C303.2 C304.2 C305.2(NEG) C310.2(NEG) C311.2 C327.2 C328.2 C330.2 C332.2 C336.2 C339.2 C340.2 C343.2 C348.2 C349.2 C360.2 C361.2 C362.2 C363.2 C364.2 C365.2 C367.2 C368.2 C373.2 C418.2 C430.2 C431.2 C434.2 C435.2 C437.2 C438.2 D1.1(Cathode) D2.1(Cathode) D3.2(ANODE) J1.9 J1.15 J1.16 J2.3 J5.2 J5.3 J6.3 J7.6(VSS) J7.9(GND) J7.11(GND3) J7.12(GND4) J7.13(GND5) J7.14(GND6) J7.15(GND7) J7.16(GND8) J10.4 J23.5 J23.6 J30.12 J30.39 J30.40 Q1.S(SOURCE) Q4.S(SOURCE) Q7.S(SOURCE) Q8.S(SOURCE) Q9.S(SOURCE) Q10.S(SOURCE) Q11.S(SOURCE) Q12.S(SOURCE) Q13.S(SOURCE) Q14.S(SOURCE) R87.1(P1) R91.1(P1) R97.1(P1) R115.1(P1) R127.1(P1) R131.1(P1) R176.1(P1) R190.1(P1) R236.1(P1) R286.2(P2) R326.1(P1) R330.1(P1) R382.1(P1) R460.1(P1) R462.1(P1) R464.1(P1) R470.1(P1) R472.1(P1) R474.1(P1) R477.1(P1) R478.1(P1) R480.1(P1) R484.1(P1) R485.1(P1) R548.1(P1) SW1.1 SW1.2 SW2.M1 SW2.M2 SW3.1 SW3.2 SW10.1 SW10.2 SW13.1 SW13.2 TP3.1 TP4.1 TP9.1 TP23.1 U1.2(GND) U5.1(A1) U5.2(A0) U5.7(GND) U18.1(A1) U18.7(GND) U20.4(GND) U20.5(A2) U22.3(GND) U23.11(GND) U23.12(GND) U23.13(GND) U25.11(GND) U32.5(GND) U32.10(RSV0) U32.12(GND) U32.13(GND) U32.16(GND) U39.M1 U39.M2 U51.4(GND) U53.5(GND) U56.TPAD(GNDP) U59.AD4(VSS_RTC) U62.B4(SYNC) U62.C1(PGND) U62.C2(PGND) U62.C3(GND) U62.D3(GND) U62.E4(GND) U63.13(GND) U63.25(GND) U63.36(GND) U63.48(GND) U65.G2(VSS) U65.G3(VSS) U65.G4(VSS) U65.G5(VSS) U65.G6(VSS) U65.G7(VSS) U65.G8(VSS) U65.G9(VSS) U65.H2(VSSQ) U65.H9(VSSQ) U65.L3(VSSQ) U65.L8(VSSQ) U65.M4(VSSQ) U65.M7(VSSQ) U65.P2(VSSQ) U65.P9(VSSQ) U74.3(GND) U76.2(GND) ; also on sheet 1 2 4 5 6 7 8 9 10 11 12 14 15 16 17 18
GND_OSC0: C180.2 C186.2 R286.1(P1) U59.B24(VSS_OSC)
V1_0BAT: C66.1 L7.2 U56.21(FB5) ; also on sheet 17
V1_8BAT: C438.1 R549.2(P2) R550.1(P1) U76.5(OUT) ; also on sheet 17
V1_8D: R335.1(P1) R364.2(P2) U22.5(VCC) ; also on sheet 2 3 4 12 17 18
V3_3D: C6.1 C13.1 C17.1 C22.1 C84.1 C106.1 C155.1 C211.1 C212.1 C215.1 C216.1 C217.1 C218.1 C219.1 C220.1 C221.1 C226.1 C227.1 C228.1 C231.1 C232.1 C233.1 C234.1 C244.1 C245.1 C311.1 C343.1 C360.1 C361.1 C362.1 C364.1 J2.1 J7.4(VDD) J10.1 J30.1 R32.2(P2) R33.2(P2) R40.2(P2) R69.2(P2) R72.2(P2) R77.2(P2) R92.2(P2) R104.2(P2) R130.2(P2) R134.2(P2) R137.2(P2) R160.2(P2) R170.2(P2) R171.2(P2) R175.2(P2) R179.2(P2) R180.2(P2) R181.2(P2) R191.2(P2) R270.2 R292.2(P2) R293.2(P2) R294.2(P2) R298.2(P2) R309.2(P2) R311.2(P2) R327.1(P1) R351.2(P2) R354.2(P2) R355.2(P2) R369.1(P1) R370.2(P2) R401.2(P2) R402.2(P2) R403.2(P2) R404.2(P2) R450.2(P2) R466.2(P2) U1.1(VDD) U5.6(VS) U18.6(VS) U20.8(V+) U23.1(VCCA) U23.23(VCCB) U23.24(VCCB) U25.2(VCCA) U25.19(VCCB) U32.1(VDD_IO) U32.14(VDD) U32.15(RSV1) U51.1(VCC) U53.10(VCC) U63.12(VCC) U63.34(VCC) U63.37(VCC) U63.39(VCC) U65.F2(VCC) U65.F3(VCC) U65.F4(VCC) U65.F5(VCC) U65.F6(VCC) U65.F7(VCC) U65.F8(VCC) U65.F9(VCC) U65.H3(VCCQ) U65.H8(VCCQ) U65.L2(VCCQ) U65.L4(VCCQ) U65.L7(VCCQ) U65.L9(VCCQ) U65.P3(VCCQ) U65.P8(VCCQ) ; also on sheet 1 2 4 5 6 7 8 9 10 11 12 14 15 16 17 18
V5_0D: C365.1 C367.1 C368.1 R381.2(P2) U56.32(IN_LS2) U62.E1(VOUT) U62.E2(VOUT) ; also on sheet 5 9 16
V5_0D_EN: R370.1(P1) U62.A4(EN)
VBAT: C37.1(POS) C61.1 C65.1 C69.1 C75.1 C76.1 C79.1 C85.1 C348.1 C349.1 J1.2 J1.4 J30.2 R7.1(P1) R85.2(P2) R95.2(P2) R96.2(P2) R113.2 R222.2(P2) R259.2(P2) R260.2(P2) R261.2(P2) R263.2(P2) R264.2(P2) R265.2(P2) R266.2(P2) R267.2(P2) U56.1(IN_DCDC1) U56.5(IN_LDO1) U56.12(IN_DCDC4) U56.27(IN_BU) U56.36(IN_BIAS) U56.37(IN_DCDC3) U56.43(IN_DCDC2) U62.A1(VIN) U62.A2(VIN) ; also on sheet 1 3 4 5 11 12 18
VBAT1_SW: TP21.1 U56.7(LS3)
VDDS_RTC: R79.2(P2) R344.1(P1) ; also on sheet 17
VINT_LDO: C49.1 C418.1 U56.35(INT_LDO) U74.5(VCC)
ACCEL_INT1: R119.2(P2) U32.11(INT1)
ACCEL_INT2: R109.2(P2) U32.9(INT2)
AM437X_AIN7: R2.1(P1) ; also on sheet 3
AM437X_CSN1: R366.2(P2) U59.B9(GPMC_CSN1/MMC1_CLK)
AM437X_CSN2: R368.2(P2) U59.F10(GPMC_CSN2/MMC1_CMD)
AM437X_HDMI_INTn: U59.N20(SPI2_SCLK) ; also on sheet 5
AM437X_HDQ_MONITOR: J30.19 R1.1(P1) U59.AB25(CAM1_WEN)
AM437X_I2C1_SCL: R125.1(P1) R355.1(P1) U59.T20(SPI0_CS0/I2C1_SCL)
AM437X_I2C1_SDA: R123.1(P1) R354.1(P1) U59.T21(SPI0_D1/I2C1_SDA)
AM437X_KEY_PWRA: J30.7 R483.2(P2) U59.K23(MCASP0_FSR/GPIO)
AM437X_KEY_PWRB: J30.9 R486.2(P2) U59.M25(MCASP0_AXR1/GPIO)
AM437X_KEY_SCN0: J30.3 R262.2(P2) U59.L24(MCASP0_AHCLKX/GPIO)
AM437X_KEY_SCN1: J30.11 R469.2(P2) U59.AD17(CAM0_WEN)
AM437X_KEY_SCN2: J30.13 R468.2(P2) U59.AC18(CAM0_FIELD)
AM437X_MMC0_CLK: R152.2(P2) U59.D1(MMC0_CLK)
AM437X_MMC0_CMD: R150.2(P2) U59.D2(MMC0_CMD)
AM437X_MMC0_DAT0: R149.2(P2) U59.C1(MMC0_DAT0)
AM437X_MMC0_DAT1: R147.2(P2) U59.C2(MMC0_DAT1)
AM437X_MMC0_DAT2: R144.2(P2) U59.B2(MMC0_DAT2)
AM437X_MMC0_DAT3: R142.2(P2) U59.B1(MMC0_DAT3)
AM437X_MMC0_SDCD: R353.2(P2) U59.R25(SPI0_CS1/MMC0_SDCD)
AM437X_NAND_AD0: U23.3(A1) U25.1(A1) U59.B5(GPMC_AD0)
AM437X_NAND_AD1: U23.4(A2) U25.3(A2) U59.A5(GPMC_AD1)
AM437X_NAND_AD2: U23.5(A3) U25.4(A3) U59.B6(GPMC_AD2)
AM437X_NAND_AD3: U23.6(A4) U25.5(A4) U59.A6(GPMC_AD3)
AM437X_NAND_AD4: U23.7(A5) U25.6(A5) U59.B7(GPMC_AD4)
AM437X_NAND_AD5: U23.8(A6) U25.7(A6) U59.A7(GPMC_AD5)
AM437X_NAND_AD6: U23.9(A7) U25.8(A7) U59.C8(GPMC_AD6)
AM437X_NAND_AD7: U23.10(A8) U25.9(A8) U59.B8(GPMC_AD7)
AM437X_NAND_WPn: R359.2(P2) U59.B3(GPMC_WPn)
AM437X_NMIn: C431.1 R93.1(P1) R466.1(P1) SW3.3 SW3.4 U59.G25(NMIn)
AM437X_OSC0_IN: R143.1(P1) U59.C25(OSC0_IN)
AM437X_OSC0_OUT: R135.1(P1) U59.B25(OSC0_OUT)
AM437X_PORZn: R108.1(P1) U59.Y23(PORZn)
AM437X_STATUS_LED0: J30.5 R476.2(P2) U59.L23(MCASP0_ACLKR/GPIO)
AM437X_STATUS_LED1: J30.23 R134.1(P1) R475.2(P2) U59.N23(JTAG_EMU0) ; also on sheet 1
AM437X_STATUS_LED2: J30.25 R351.1(P1) R473.2(P2) U59.T24(JTAG_EMU1) ; also on sheet 1
AM437X_STATUS_LED3: J30.31 R465.2(P2) U59.G20(GPIO5_10)
AM437X_STATUS_LED4: J30.33 R463.2(P2) U59.F23(GPIO5_11)
AM437X_STATUS_LED5: J30.35 R461.2(P2) U59.E25(GPIO5_12) ; also on sheet 17
AM437X_STATUS_LED6: J30.37 R481.2(P2) U59.E24(GPIO5_13)
AM437X_STATUS_LED7: J30.22 R479.2(P2) U59.P25(GPIO5_4)
BAT_HDQ: J1.13 R1.2(P2)
BUZZER_N: Q1.D(DRAIN) SPKR1.2(NEG-)
BUZZER_P: R113.1 SPKR1.1(POS+)
CTPM_TESTOUT: TP15.1 U59.AD11(RSV)
EMMC_DAT0: R181.1(P1) U25.20(B1) U65.K2(DAT0)
EMMC_DAT1: R180.1(P1) U25.18(B2) U65.N2(DAT1)
EMMC_DAT2: R179.1(P1) U25.17(B3) U65.K3(DAT2)
EMMC_DAT3: R401.1(P1) U25.16(B4) U65.N3(DAT3)
EMMC_DAT4: R404.1(P1) U25.15(B5) U65.N8(DAT4)
EMMC_DAT5: R402.1(P1) U25.14(B6) U65.K8(DAT5)
EMMC_DAT6: R175.1(P1) U25.13(B7) U65.N9(DAT6)
EMMC_DAT7: R403.1(P1) U25.12(B8) U65.K9(DAT7)
EMMC_RSTn: R173.2(P2) U65.M5(RSTn)
EP_PIO_0: J23.1 U59.AC12(RSV)
EP_PIO_1: J23.3 U59.AC9(RSV)
EP_PIO_2: J23.2 U59.AC10(RSV)
EP_PIO_3: J23.4 U59.Y7(RSV)
GP_I2C_SCL: J10.2 J30.24 R80.2(P2) R125.2(P2) U1.3(SMBCLK) U20.2(SCL) U32.4(SCL/SPC) ; also on sheet 2 4 5 12
GP_I2C_SDA: J10.3 J30.26 R70.2(P2) R123.2(P2) U1.4(SMBDATA) U20.1(SDA) U32.6(SDA/SDI/SDO) ; also on sheet 2 4 5 12
GPIO7: J30.17 U59.T22(SPI0_D0/GPIO)
GPIO12: J30.27 R360.1(P1) U59.D25(GPIO5_8)
GPIO13: J30.29 R357.1(P1) U59.F24(GPIO5_9)
GPIO19: J30.28 R118.1(P1) U59.R24(GPIO5_5)
GPIO20: J30.30 R119.1(P1) U59.P24(GPIO5_6)
GPIO21: J30.32 R120.1(P1) U59.N25(GPIO5_7)
GPIO23: J30.36 R109.1(P1) U59.P20(SPI2_D1)
GPIO24: J30.38 R121.1(P1) U59.T23(SPI2_CS0)
GPIO_AUDIO_BUZZER_TRIG: J30.21 R114.1(P1) U59.AC25(CAM1_FIELD)
GPIO_HAPTICS_TRIG: J30.15 R235.1(P1) U59.P23(SPI0_SCLK/GPIO)
GPIO_VTTEN: R120.2(P2) ; also on sheet 15
HAPTICS_N: Q4.D(DRAIN) U39.2(N-)
HAPTICS_P: C271.1 R222.1(P1) U39.1(P+)
I2C0_SCL: R77.1(P1) R80.1(P1) U56.3(SCL) U59.Y22(I2C_SCL0) ; also on sheet 10 11
I2C0_SDA: R70.1(P1) R72.1(P1) U56.2(SDA) U59.AB24(I2C_SDA0) ; also on sheet 10 11
KEYPAD_PWRA: R483.1(P1) SW4.1 SW4.2 SW5.1 SW5.2 SW6.1 SW6.2
KEYPAD_PWRB: R486.1(P1) SW7.1 SW7.2 SW8.1 SW8.2 SW9.1 SW9.2
KEYPAD_SCN0: C435.1 R262.1(P1) R485.2(P2) SW4.3 SW4.4 SW7.3 SW7.4
KEYPAD_SCN1: C434.1 R469.1(P1) R484.2(P2) SW5.3 SW5.4 SW8.3 SW8.4
KEYPAD_SCN2: C430.1 R468.1(P1) R470.2(P2) SW6.3 SW6.4 SW9.3 SW9.4
LOWPOWERn: R117.2(P2) R450.1(P1) ; also on sheet 5
MMC_CD: J7.10(CD) R292.1(P1) R353.1(P1) U51.3(IO1)
MMC_CLK: J7.5(CLOCK) R152.1(P1) U53.1(IO1)
MMC_CMD: J7.3(CMD) R150.1(P1) R294.1(P1) U53.7(IO5)
MMC_D0: J7.7(DAT0) R149.1(P1) R309.1(P1) U53.2(IO2)
MMC_D1: J7.8(DAT1) R147.1(P1) R311.1(P1) U53.3(IO3)
MMC_D2: J7.1(DAT2) R144.1(P1) R293.1(P1) U53.6(IO4)
MMC_D3: J7.2(CD/DAT3) R142.1(P1) R298.1(P1) U53.8(IO6)
NAND_ADVN_ALE: R384.1(P1) U63.17(ALE)
NAND_BE0n_CLE: R383.1(P1) U63.16(CLE)
NAND_CSn: R160.1(P1) R371.1(P1) U63.9(\\~{CE})
NAND_D0: U23.21(B1) U63.29(I/O0)
NAND_D1: U23.20(B2) U63.30(I/O1)
NAND_D2: U23.19(B3) U63.31(I/O2)
NAND_D3: U23.18(B4) U63.32(I/O3)
NAND_D4: U23.17(B5) U63.41(I/O4)
NAND_D5: U23.16(B6) U63.42(I/O5)
NAND_D6: U23.15(B7) U63.43(I/O6)
NAND_D7: U23.14(B8) U63.44(I/O7)
NAND_OEn: R367.1(P1) U23.2(DIR) U63.8(\\~{R}E)
NAND_WAIT: R364.1(P1) R365.1(P1) U63.7(R~{/B})
NAND_WEn: R385.1(P1) U63.18(\\~{W}E)
NAND_WPn: R170.1(P1) R171.1(P1) R173.1(P1) U22.4(Y) U63.19(\\~{W}P)
OSC0_IN: C186.1 R140.2(P2) R143.2(P2) Y4.3
OSC0_OUT: C180.1 R135.2(P2) R140.1(P1) Y4.1
PM_ALERT: J6.4 R40.1(P1) U5.3(ALERT) U18.3(ALERT)
PM_AM437X_V1_8DN: C58.2 J26.2 ; also on sheet 17
PM_AM437X_V1_8DP: C58.1 J26.1 ; also on sheet 17
PM_AM437X_V3_3DN: C200.2 J34.2 ; also on sheet 17
PM_AM437X_V3_3DP: C200.1 J34.1 ; also on sheet 17
PM_VDDCOREN: C14.2 U5.9(VIN-) ; also on sheet 17
PM_VDDCOREP: C14.1 U5.10(VIN+) ; also on sheet 17
PM_VDDMPUN: C92.2 U18.9(VIN-) ; also on sheet 17
PM_VDDMPUP: C92.1 U18.10(VIN+) ; also on sheet 17
PM_VDDSAM437XDDRN: C99.2 J32.2 ; also on sheet 17
PM_VDDSAM437XDDRP: C99.1 J32.1 ; also on sheet 17
PM_VDDSDDRN: C324.2 J24.2 ; also on sheet 15
PM_VDDSDDRP: C324.1 J24.1 ; also on sheet 15
PMIC_AC_DET: J1.14 R95.1(P1) R97.2(P2) U56.9(AC_DET)
PMIC_IN_nCC: R83.2(P2) U56.18(IN_nCC)
PMIC_INTn: R92.1(P1) R93.2(P2) U56.45(INTn)
PMIC_L5: L7.1 U56.20(L5)
PMIC_L6: L6.1 U56.23(L6)
PMIC_LDO1: C340.1 R335.2(P2) U56.4(LDO1)
PMIC_PFI: R91.2(P2) R96.1(P1) U56.16(PFI)
PMIC_PGOOD: R98.2(P2) U56.8(PGOOD)
PMIC_PGOODBU: R82.2(P2) U56.19(PGOOD_BU)
PMIC_PWR_EN: R346.1(P1) U56.46(PWR_EN)
PMIC_SYS_BU: C330.1 R551.2(P2) U56.24(SYS_BU)
PMIC_WAKEUPn: R76.2(P2) R79.1(P1) U56.40(WAKEUPn)
PMU_PORZn: J1.5 R82.1(P1) R337.1(P1)
PORZn: C59.1 R69.1(P1) R98.1(P1) R108.2(P2) R482.2(P2) U74.2(A)
PWRMON_I2CSCL: J6.1 R33.1(P1) U5.5(SCL) U18.5(SCL)
PWRMON_I2CSDA: J6.2 R32.1(P1) U5.4(SDA) U18.4(SDA)
SEL_eMMCORNANDn: J2.2 R121.2(P2) R176.2(P2) U23.22(~{OE}) U25.10(OE)
SEL_LCDORHDMIn: R360.2(P2) ; also on sheet 4 5
SYS_RESETn: R449.1(P1) ; also on sheet 1 4 5 10 14
SYS_WARMRESETn: C373.1 R136.2(P2) R137.1(P1) R399.1(P1) R449.2(P2) U74.4(Y)
TEMPSENSOR_ALERT: R118.2(P2) R130.1(P1) U20.3(ALERT)
TM_TESTOUT: TP16.1 U59.AD10(RSV)
TOUCH_INTn: J30.34 U59.P22(SPI2_D0) ; also on sheet 4
USB0_VBUS_DET: R357.2(P2) ; also on sheet 16
USB5V_FB: R381.1(P1) R382.2(P2) U62.E3(FB)
VDCDC1: C18.1 C339.1 L9.2 U5.8(VBUS) U56.47(FB1) ; also on sheet 17
VDCDC2: C100.1 C332.1 L8.2 U18.8(VBUS) U56.41(FB2) ; also on sheet 17
VDCDC3: C327.1 L5.2 R304.2(P2) U56.31(IN_LS1) U56.39(FB3) ; also on sheet 15
VDCDC4: C336.1 R327.2(P2) U56.15(DCDC4)
VLS1: C328.1 U56.30(LS1) ; also on sheet 17
VPMIC_LS2: R313.2(P2) U56.33(LS2)
VPWR_IN: C301.1 C302.1 C303.1 C304.1 C305.1(POS) C310.1(POS) J1.1 J1.3 R7.2(P2) R269.2(P2) SW2.2 TP10.1 U56.6(IN_LS3)
VPWRIN_FUSED: D3.1(CATHODE) F1.2 SW2.1
VPWRIN_JCK: D4.2(ANODE) J5.1
VPWRIN_PREFUSE: D4.1(CATHODE) F1.1
VUSB_VBUS0: R313.1(P1) ; also on sheet 16
WAKEUP0: R76.1(P1) R343.1(P1)
N10692191: R399.2(P2) SW13.3 SW13.4
N11290910: R136.1(P1) U59.G22(RESETIN_OUTn)
N11520122: TP13.1 U59.AD7(RSV)
N11520158: C97.2 R107.2(P2) Y3.1
N11520166: R107.1(P1) U59.AE12(RSV)
N11520178: C96.2 U59.AE11(RSV) Y3.4
N11520288: R330.2(P2) U59.AE10(VSS)
N11520324: TP14.1 U59.AE7(RSV)
N11854504: R482.1(P1) SW10.3 SW10.4
N12221112: R191.1(P1) U32.8(CS)
N12221116: R190.2(P2) U32.7(SDO/SA0)
N12369102: J29.1 U59.AD1(VSS)
N12686071: R371.2(P2) U59.A8(GPMC_CS0n)
N12686075: R384.2(P2) U59.A9(GPMC_ADVN_ALE)
N12686079: R367.2(P2) U59.E10(GPMC_OEN_REN)
N12686083: R385.2(P2) U59.D10(GPMC_WEN/GPIO)
N12686087: R383.2(P2) U59.C10(GPMC_BE0N_CLE)
N12686111: R365.2(P2) U59.A2(GPMC_WAIT0)
N12733905: R127.2(P2) U20.7(A0)
N12733913: R131.2(P2) U20.6(A1)
N12734329: Q1.G(GATE) R114.2(P2) R115.2(P2)
N12734771: Q4.G(GATE) R235.2(P2) R236.2(P2)
N14122798: Q12.G(GATE) R476.1(P1) R477.2(P2)
N14122802: Q11.G(GATE) R474.2(P2) R475.1(P1)
N14122806: Q10.G(GATE) R472.2(P2) R473.1(P1)
N14122814: Q9.G(GATE) R464.2(P2) R465.1(P1)
N14123228: D12.1(Cathode) Q12.D(DRAIN)
N14123236: D12.2(Anode) R263.1(P1)
N14123256: D13.1(Cathode) Q11.D(DRAIN)
N14123268: D13.2(Anode) R264.1(P1)
N14123284: D14.2(Anode) R265.1(P1)
N14123288: D14.1(Cathode) Q10.D(DRAIN)
N14123296: D9.1(Cathode) Q9.D(DRAIN)
N14123312: D9.2(Anode) R259.1(P1)
N14179015: R104.1(P1) U18.2(A0)
N14563512: R85.1(P1) SW1.3 SW1.4 U56.44(PB)
N14564060: C55.1 L6.2 R550.2(P2) U56.22(FB6)
N14564212: C54.1 J25.2 R61.2 U56.25(CC)
N14564240: BT1.1(Pos) J25.1 R61.1
N14564626: TP20.1 U56.11(GPIO1)
N14564630: R304.1(P1) TP11.1 U56.34(GPO2)
N14564740: R87.2(P2) U56.17(DC34_SEL)
N14565284: L10.1 U56.13(L4A)
N14565288: L5.1 U56.38(L3)
N14565304: L8.1 U56.42(L2)
N14565320: L9.1 U56.48(L1)
N14565872: L10.2 U56.14(L4B)
N14568234: L11.1 U62.B1(L1) U62.B2(L1)
N14568254: L11.2 U62.D1(L2) U62.D2(L2)
N14568274: C363.1 U62.A3(VINA) U62.B3(VINA1) U62.C4(~{PS}) U62.D4(VSEL)
N14677780: R359.1(P1) U22.2(A)
N14699899: R366.1(P1) U65.P6(CLK)
N14699960: R368.1(P1) R369.2(P2) U65.P5(CMD)
N14719514: D2.2(Anode) R269.1(P1)
N14719805: D1.2(Anode) R270.1
N15652211: Q8.G(GATE) R462.2(P2) R463.1(P1)
N15652215: Q7.G(GATE) R460.2(P2) R461.1(P1)
N15652219: Q14.G(GATE) R480.2(P2) R481.1(P1)
N15652227: Q13.G(GATE) R478.2(P2) R479.1(P1)
N15652267: D10.1(Cathode) Q8.D(DRAIN)
N15652281: D10.2(Anode) R260.1(P1)
N15652301: D11.1(Cathode) Q7.D(DRAIN)
N15652313: D11.2(Anode) R261.1(P1)
N15652329: D15.2(Anode) R266.1(P1)
N15652333: D15.1(Cathode) Q14.D(DRAIN)
N15652341: D16.1(Cathode) Q13.D(DRAIN)
N15652357: D16.2(Anode) R267.1(P1)
N16155764: J30.14 U59.N24(MCASP0_ACLKX/SPI1_SCLK)
N16155776: J30.16 U59.N22(MCASP0_FSX/SPI1_D0)
N16155788: J30.18 U59.H23(MCASP0_AXR0/SPI1_D1)
N16155800: J30.20 U59.M24(MCASP0_AHCLKR/SPI1_CS0)
N16927149: C213.1 U65.E4(VDDIM)
N17340566: J1.11 R2.2(P2)
N17832251: R106.1(P1) U59.AE4(OSC1_OUT)
N17832253: C94.1 R106.2(P2) Y2.4
N17832259: C95.1 U59.AE5(OSC1_IN) Y2.1
N17957689: R344.2(P2) U59.AE2(RTC_KALDO_EN)
N17957695: R346.2(P2) U59.AD6(RTC_PMIC_EN)
N17957723: R343.2(P2) U59.AE3(RTC_WAKEUP)
N17957870: R337.2(P2) U59.AE6(RTC_PORZ)
N17986228: J29.2 U59.AD2(VSS)
N18289721: R326.2(P2) U59.AE8(VSS)
N18994118: R117.1(P1) U59.H20(CLKREQ/GPIO0_24)
N19255466: C437.1 R551.1(P1) U76.1(IN) U76.3(EN)
N19255489: R548.2(P2) R549.1(P1) U76.4(FB)

Not connected (* = marked no-connect by the designer): J1 6* 7* 8* 10* 12*; J6 5; J30 4 6 8 10; R83 1(P1)*; SW2 3*; U22 1(NC); U32 2(NC0) 3(NC1); U51 2(NC)* 5(IO2); U53 4(NC1)* 9(NC2)*; U56 10(PFOn)* 26(GPIO3) 28(RSV1)* 29(RSV2)*; U59 AA7(RSV) AA9(RSV) AA10(RSV) AB6(RSV) AB7(RSV) AB9(RSV)* AB10(RSV) AC5(RSV) AC6(RSV) AC7(RSV)* AE9(RSV) H19(RSV) W10(RSV)* Y6(RSV)* Y10(RSV); U63 1(NC-1)* 2(NC-2)* 3(NC-3)* 4(NC-4)* 5(NC-5)* 6(NC-6)* 10(NC-7)* 11(NC-8)* 14(NC-9)* 15(NC-10)* 20(NC-11)* 21(NC-12)* 22(NC-13)* 23(NC-14)* 24(NC-15)* 26(NC_IO8) 27(NC_IO9) 28(NC_IO10) 33(NC_IO11) 35(NC16)* 38(NC17)* 40(NC_IO12) 45(NC_IO13) 46(NC_IO14) 47(NC_IO15); U65 A1(NCA1) A2(NCA2) A9(NCA9) A10(NCA10) B1(NCB1) B10(NCB10) D2(NCD2) D3(NCD3) D4(NCD4) D5(NCD5) D6(NCD6) D7(NCD7) D8(NCD8) D9(NCD9) E2(NCE2) E3(NCE3) E5(NCE5) E6(NCE6) E7(NCE7) E8(NCE8) E9(NCE9) H4(NCH4) H5(NCH5) H6(NCH6) H7(NCH7) J2(NCJ2) J3(NCJ3) J4(NCJ4) J5(NCJ5) J6(NCJ6) J7(NCJ7) J8(NCJ8) J9(NCJ9) K4(NCK4) K5(NCK5) K6(NCK6) K7(NCK7) L5(NCL5) L6(NCL6) M2(NCM2) M3(NCM3) M6(NCM6) M8(NCM8) M9(NCM9) N4(NCN4) N5(NCN5) N6(NCN6) N7(NCN7) P4(NCP4) P7(NCP7) T1(NCT1) T10(NCT10) U1(NCU1) U2(NCU2) U9(NCU9) U10(NCU10); U74 1(NC)*; Y2 2* 3*; Y3 2* 3*; Y4 2(NC0)* 4(NC1)*

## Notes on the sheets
sheet 19
- Key Pad - Top Side
- Status LED's
sheet 22
- SD/MMC0 Connector
sheet 23
- Main Power Input
- Battery Board
  Connector
- Coin Cell
sheet 24
- User Interrupt Switch
- Reset Switch
- Warm Reset Switch
sheet 25
- NAND Memory
- eMMC Memory
